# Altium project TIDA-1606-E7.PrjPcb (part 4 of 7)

## Sheet TIDA-1606-Switching-Node-L3-E7.SchDoc
size A2; Date: Not shown in title block; ApprovedBy: Not shown in title block; CheckedBy: Not shown in title block; Author: Not shown in title block; CompanyName: Not shown in title block; Engineer: Not shown in title block; Organization: Not shown in title block; Address1: Not shown in title block; Address2: Not shown in title block; Address3: Not shown in title block; Address4: Not shown in title block; DocumentNumber: 13; Revision: Use project parameter SCH_Rev; SheetNumber: 13; SheetTotal: 16; PageSetup: Record=PageOptions¦CenterHorizontal=True¦CenterVertical=True¦PrintScale=0.69¦XCorrection=1.00¦YCorrection=1.00¦PrintKind=0¦BorderSize=5000000¦LeftOffset=0¦BottomOffset=0¦Orientation=2¦PaperLength=1000¦PaperWidth=1000¦Scale=100¦PaperSource=15¦PrintQuality=600¦MediaType=1¦DitherType=10¦PaperKind=Letter¦PrintScaleMode=1
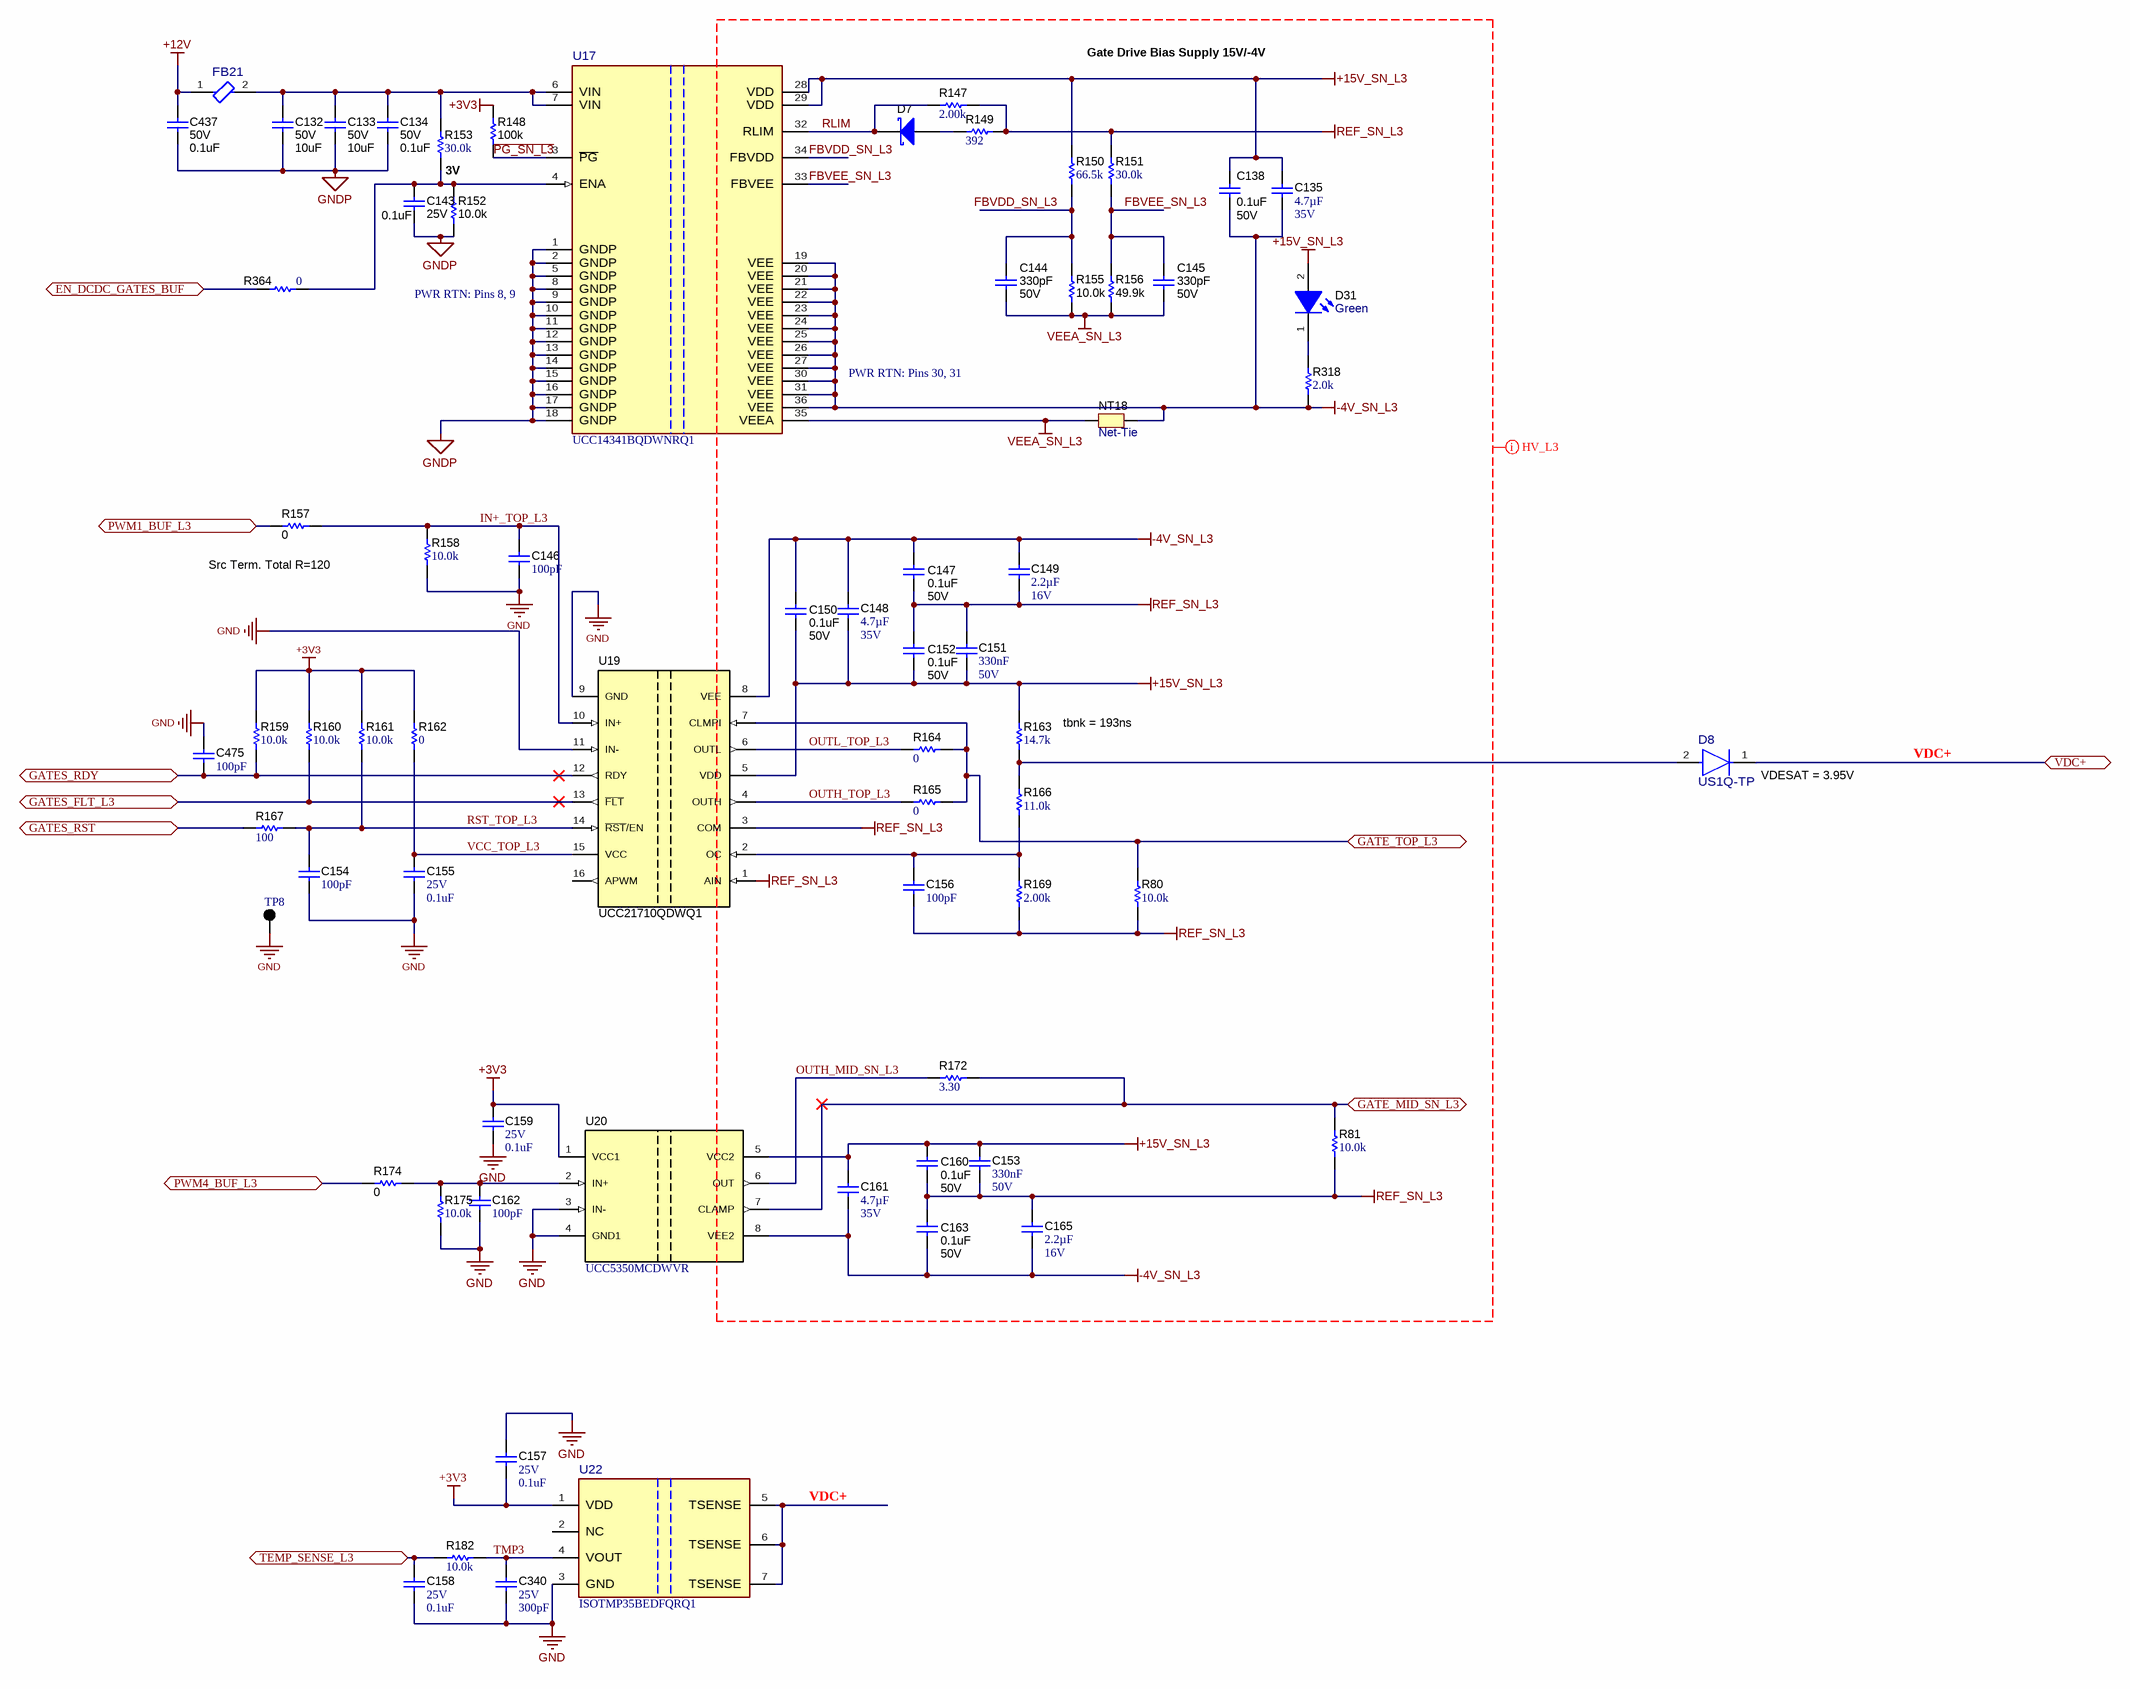
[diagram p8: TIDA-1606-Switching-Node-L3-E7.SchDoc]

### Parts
C132  VDC_V: 50V  ValueDisplayed: 10uF  [1206_180L]  (hidden comment: CL31B106KBHNNNE)
C133  VDC_V: 50V  ValueDisplayed: 10uF  [1206_180L]  (hidden comment: CL31B106KBHNNNE)
C134  VDC_V: 50V  ValueDisplayed: 0.1uF  [0402S]  (hidden comment: GCM155R71H104KE02D)
C135  Cap_F: 4.7µF  VDC_V: 35V  [0805_HV]  (hidden comment: C2012X7R1V475K125AC)
C138  VDC_V: 50V  ValueDisplayed: 0.1uF  [0402L]  (hidden comment: GCM155R71H104KE02D)
C143  VDC_V: 25V  ValueDisplayed: 0.1uF  [0402S]  (hidden comment: GRM155R71E104KE14D)
C144  VDC_V: 50V  ValueDisplayed: 330pF  [0402S]  (hidden comment: CGA2B2X7R1H331K050BA)
C145  VDC_V: 50V  ValueDisplayed: 330pF  [0402S]  (hidden comment: CGA2B2X7R1H331K050BA)
C146  ValueDisplayed: 100pF  [0402L]  (hidden comment: GRM1555C1H101JA01D)
C147  VDC_V: 50V  ValueDisplayed: 0.1uF  [0402L]  (hidden comment: GCM155R71H104KE02D)
C148  Cap_F: 4.7µF  VDC_V: 35V  [0805_HV]  (hidden comment: C2012X7R1V475K125AC)
C149  Cap_F: 2.2µF  VDC_V: 16V  [0603L]  (hidden comment: EMK107BB7225KA-T)
C150  VDC_V: 50V  ValueDisplayed: 0.1uF  [0402L]  (hidden comment: GCM155R71H104KE02D)
C151  Cap_F: 330nF  VDC_V: 50V  [0603L]  (hidden comment: C1608X7R1H334K080AC)
C152  VDC_V: 50V  ValueDisplayed: 0.1uF  [0402L]  (hidden comment: GCM155R71H104KE02D)
C153  Cap_F: 330nF  VDC_V: 50V  [0603L]  (hidden comment: C1608X7R1H334K080AC)
C154  ValueDisplayed: 100pF  [0402L]  (hidden comment: GRM1555C1H101JA01D)
C155  VDC_V: 25V  ValueDisplayed: 0.1uF  [0402L]  (hidden comment: GRM155R71E104KE14D)
C156  ValueDisplayed: 100pF  [0402L]  (hidden comment: GRM1555C1H101JA01D)
C157  VDC_V: 25V  ValueDisplayed: 0.1uF  [0402L]  (hidden comment: GRM155R71E104KE14D)
C158  VDC_V: 25V  ValueDisplayed: 0.1uF  [0402L]  (hidden comment: GRM155R71E104KE14D)
C159  VDC_V: 25V  ValueDisplayed: 0.1uF  [0402L]  (hidden comment: GRM155R71E104KE14D)
C160  VDC_V: 50V  ValueDisplayed: 0.1uF  [0402L]  (hidden comment: GCM155R71H104KE02D)
C161  Cap_F: 4.7µF  VDC_V: 35V  [0805_HV]  (hidden comment: C2012X7R1V475K125AC)
C162  ValueDisplayed: 100pF  [0402L]  (hidden comment: GRM1555C1H101JA01D)
C163  VDC_V: 50V  ValueDisplayed: 0.1uF  [0402L]  (hidden comment: GCM155R71H104KE02D)
C165  Cap_F: 2.2µF  VDC_V: 16V  [0603L]  (hidden comment: EMK107BB7225KA-T)
C340  VDC_V: 25V  ValueDisplayed: 300pF  [0402L]  (hidden comment: GRM1555C1E301JA01D)
C437  VDC_V: 50V  ValueDisplayed: 0.1uF  [0402S]  (hidden comment: GCM155R71H104KE02D)
C475  ValueDisplayed: 100pF  [0402L]  (hidden comment: GRM1555C1H101JA01D)
D7  NSR0130P2T5G  [SOD-923]  (value not drawn)
D8  US1Q-TP  [FP-US1Q-TP_SMA-MFG]
D31  value Green  [WL-SMCW_GREEN]  (hidden comment: 150060VS75000)
FB21  74269244182  [FP-74269244182_0402-MFG]  (value not drawn)
NT18  Net-Tie  [Net-Tie7milsWide_20milsLong]  (net tie, no BOM)
R80  ValueDisplayed: 10.0k  [0402L]  (hidden comment: CRCW040210K0FKED)
R81  ValueDisplayed: 10.0k  [0402L]  (hidden comment: CRCW040210K0FKED)
R147  ValueDisplayed: 2.00k  [0402L]  (hidden comment: CRCW04022K00FKED)
R148  ValueDisplayed: 100k  [0402S]  (hidden comment: ERJ-2GEJ104X)
R149  ValueDisplayed: 392  [0402L]  (hidden comment: CRCW0402392RFKED)
R150  ValueDisplayed: 66.5k  [0402L]  (hidden comment: CRCW040266K5FKED)
R151  ValueDisplayed: 30.0k  [0402L]  (hidden comment: CRCW040230K0FKED)
R152  ValueDisplayed: 10.0k  [0402S]  (hidden comment: MCS0402MD1002BE100)
R153  ValueDisplayed: 30.0k  [0402L]  (hidden comment: CRCW040230K0FKED)
R155  ValueDisplayed: 10.0k  [0402S]  (hidden comment: MCS0402MD1002BE100)
R156  ValueDisplayed: 49.9k  [0402S]  (hidden comment: PCF0402-03-49K9BT1)
R157  ValueDisplayed: 0  [0603L]  (hidden comment: RCS06030000Z0EA)
R158  ValueDisplayed: 10.0k  [0402L]  (hidden comment: CRCW040210K0FKED)
R159  ValueDisplayed: 10.0k  [0402L]  (hidden comment: CRCW040210K0FKED)
R160  ValueDisplayed: 10.0k  [0402L]  (hidden comment: CRCW040210K0FKED)
R161  ValueDisplayed: 10.0k  [0402L]  (hidden comment: CRCW040210K0FKED)
R162  ValueDisplayed: 0  [0603L]  (hidden comment: RC0603JR-070RL)
R163  ValueDisplayed: 14.7k  [0603L]  (hidden comment: ERJ-3EKF1472V)
R164  ValueDisplayed: 0  [1206]  (hidden comment: CRCW12060000Z0EA)
R165  ValueDisplayed: 0  [1206]  (hidden comment: CRCW12060000Z0EA)
R166  ValueDisplayed: 11.0k  [0603L]  (hidden comment: RC0603FR-0711KL)
R167  ValueDisplayed: 100  [0402L]  (hidden comment: ERJ-2RKF1000X)
R169  ValueDisplayed: 2.00k  [0402L]  (hidden comment: CRCW04022K00FKED)
R172  ValueDisplayed: 3.30  [1206]  (hidden comment: ERJ-8RQF3R3V)
R174  ValueDisplayed: 0  [0603L]  (hidden comment: RCS06030000Z0EA)
R175  ValueDisplayed: 10.0k  [0402L]  (hidden comment: CRCW040210K0FKED)
R182  ValueDisplayed: 10.0k  [0402L]  (hidden comment: CRCW040210K0FKED)
R318  ValueDisplayed: 2.0k  [1206]  (hidden comment: CRCW12062K00JNEA)
R364  ValueDisplayed: 0  [0402L]  (hidden comment: RC0402JR-070RL)
TP8  5001  [Keystone5001]  (value not drawn)
U17  UCC14341BQDWNRQ1  [DWN0036A-MFG]
U19  UCC21710QDWQ1  [DW0016B_HV]
U20  UCC5350MCDWVR  [DWV0008A]
U22  ISOTMP35BEDFQRQ1  [DFQ0007A-MFG]

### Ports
EN_DCDC_GATES_BUF (bidir), GATE_MID_SN_L3 (bidir), GATE_TOP_L3 (bidir), GATES_FLT_L3 (bidir), GATES_RDY (bidir), GATES_RST (bidir), PWM1_BUF_L3 (bidir), PWM4_BUF_L3 (bidir), TEMP_SENSE_L3 (bidir), VDC+ (bidir)

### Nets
+3V3: C157.2 C159.1 R148.2 R159.2 R160.2 R161.2 R162.2 U20.1(VCC1) U22.1(VDD)
+12V: C437.1 FB21.1
+15V_SN_L3: C135.1 C138.2 C148.2 C150.1 C151.2 C152.1 C153.1 C160.2 C161.1 D31.2(A) R150.2 R163.2 U17.28(VDD) U17.29(VDD) U19.5(VDD) U20.5(VCC2)
-4V_SN_L3: C135.2 C138.1 C147.2 C148.1 C149.1 C150.2 C161.2 C163.1 C165.2 NT18.1 R318.1 U17.19(VEE) U17.20(VEE) U17.21(VEE) U17.22(VEE) U17.23(VEE) U17.24(VEE) U17.25(VEE) U17.26(VEE) U17.27(VEE) U17.30(VEE) U17.31(VEE) U17.36(VEE) U19.8(VEE) U20.8(VEE2)
GND: C132.2 C133.2 C134.2 C143.2 C146.2 C154.2 C155.2 C157.1 C158.2 C159.2 C162.2 C340.1 C437.2 C475.1 R152.1 R158.1 R175.2 TP8.1 U17.1(GNDP) U17.2(GNDP) U17.5(GNDP) U17.8(GNDP) U17.9(GNDP) U17.10(GNDP) U17.11(GNDP) U17.12(GNDP) U17.13(GNDP) U17.14(GNDP) U17.15(GNDP) U17.16(GNDP) U17.17(GNDP) U17.18(GNDP) U19.9(GND) U19.11(IN-) U20.3(IN-) U20.4(GND1) U22.3(GND)  [also labelled GNDP]
REF_SN_L3: C147.1 C149.2 C151.1 C152.2 C153.2 C156.2 C160.1 C163.2 C165.1 R80.1 R81.1 R147.1 R149.2 R151.2 R169.1 U19.1(AIN) U19.3(COM)
VDC+: D8.1(CATHODE) U22.5(TSENSE) U22.6(TSENSE) U22.7(TSENSE) ; port VDC+
VEEA_SN_L3: C144.2 C145.2 NT18.2 R155.1 R156.1 U17.35(VEEA)
~{PG_SN_L3}: R148.1 U17.3(~{PG})
EN_DCDC_GATES_BUF: R364.1 ; port EN_DCDC_GATES_BUF
FBVDD_SN_L3: C144.1 R150.1 R155.2 U17.34(FBVDD)
FBVEE_SN_L3: C145.1 R151.1 R156.2 U17.33(FBVEE)
GATE_MID_SN_L3: R81.2 R172.2 U20.7(CLAMP) ; port GATE_MID_SN_L3
GATE_TOP_L3: R80.2 R164.2 R165.2 U19.7(CLMPI) ; port GATE_TOP_L3
GATES_FLT_L3: R160.1 U19.13(~{FLT}) ; port GATES_FLT_L3
GATES_RDY: C475.2 R159.1 U19.12(RDY) ; port GATES_RDY
GATES_RST: R167.1 ; port GATES_RST
IN+_TOP_L3: C146.1 R157.1 R158.2 U19.10(IN+)
OUTH_MID_SN_L3: R172.1 U20.6(OUT)
OUTH_TOP_L3: R165.1 U19.4(OUTH)
OUTL_TOP_L3: R164.1 U19.6(OUTL)
PWM1_BUF_L3: R157.2 ; port PWM1_BUF_L3
PWM4_BUF_L3: R174.2 ; port PWM4_BUF_L3
RLIM: D7.1(K) R147.2 U17.32(RLIM)
RST_TOP_L3: C154.1 R161.1 R167.2 U19.14(~{RST}/EN)
TEMP_SENSE_L3: C158.1 R182.2 ; port TEMP_SENSE_L3
TMP3: C340.2 R182.1 U22.4(VOUT)
VCC_TOP_L3: C155.1 R162.1 U19.15(VCC)
NetC132_1: C132.1 C133.1 C134.1 FB21.2 R153.2 U17.6(VIN) U17.7(VIN)
NetC143_1: C143.1 R152.2 R153.1 R364.2 U17.4(ENA)
NetC156_1: C156.1 R166.1 R169.2 U19.2(OC)
NetC162_1: C162.1 R174.1 R175.1 U20.2(IN+)
NetD7_2: D7.2(A) R149.1
NetD8_2: D8.2(ANODE) R163.1 R166.2
NetD31_1: D31.1(K) R318.2

Not connected (* = marked no-connect by the designer): U19 16(APWM); U22 2(NC)

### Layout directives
net class HV_L3; net class HV_Nets: +15V_SN_L3, -4V_SN_L3, FBVDD_SN_L3, FBVEE_SN_L3, OUTH_MID_SN_L3, OUTH_TOP_L3, OUTL_TOP_L3, REF_SN_L3, RLIM, VEEA_SN_L3

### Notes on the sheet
- Gate Drive Bias Supply 15V/-4V
- (near R153) 3V
- PWR RTN: Pins 8, 9
- PWR RTN: Pins 30, 31
- (near R157) Src Term. Total R=120
- (near R163) tbnk = 193ns
- (near D8) VDESAT = 3.95V

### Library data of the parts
C132 C133 = CMP-0008802-2: CAP, CERM, 10 uF, 50 V, +/- 10%, X7R, 1206; Manufacturer: Samsung; TaMin_C: -55°C; Polarized: N; SizeAreaWB_mm2: 10.92; Value1: Unknown; U/M: EA; Value: 10uF; TaMax_C: 125°C; SizeZ_mm: 1.8; SizeX_mm: 3.2; SizeY_mm: 1.6; Cap_Case: 1206; SizeArea_mm2: 5.12; Cap_F: 10µF; AEC Category: Q200
C134 C138 C147 C150 C152 C160 C163 C437 = CMP-0006356-2: CAP, CERM, 0.1 uF, 50 V, +/- 10%, X7R, AEC-Q200 Grade 1, 0402; Manufacturer: MuRata; TaMin_C: -55°C; Polarized: N; SizeAreaWB_mm2: 3; Value1: Unknown; U/M: EA; Value: 0.1uF; TaMax_C: 125°C; SizeZ_mm: 0.6; SizeX_mm: 1; SizeY_mm: 0.5; Cap_Case: 0402; AEC Qualified: Y; Cap_F: 100nF; AEC Category: Q200
C135 C148 C161 = CMP-0007885-2: CAP, CERM, 4.7 uF, 35 V, +/- 10%, X7R, 0805; Manufacturer: TDK; TaMin_C: -55°C; ESR_ohm: 2.346m; Polarized: N; SizeAreaWB_mm2: 6.75; Value1: 0.002346 ohm; U/M: EA; Value: 4.7uF; TaMax_C: 125°C; SizeZ_mm: 1.45; SizeX_mm: 2; SizeY_mm: 1.25; Cap_Case: 0805; SizeArea_mm2: 2.5; IRMS_A: 4.26021A; AEC Category: Q200
C143 C155 C157-C159 = CMP-0006659-2: CAP, CERM, 0.1 uF, 25 V, +/- 10%, X7R, 0402; Manufacturer: MuRata; TaMin_C: -55°C; Polarized: N; SizeAreaWB_mm2: 3; Value1: Unknown; U/M: EA; Value: 0.1uF; TaMax_C: 125°C; SizeZ_mm: 0.6; SizeX_mm: 1; SizeY_mm: 0.5; Cap_Case: 0402; Cap_F: 100nF; AEC Category: Q200
C144 C145 = CMP-0006318-2: CAP, CERM, 330 pF, 50 V, +/- 10%, X7R, AEC-Q200 Grade 1, 0402; Manufacturer: TDK; TaMin_C: -55°C; ESR_ohm: 6.53276; Polarized: N; SizeAreaWB_mm2: 3; Value1: 6.53276 ohm; U/M: EA; Value: 330pF; TaMax_C: 125°C; SizeZ_mm: 0.6; SizeX_mm: 1; SizeY_mm: 0.5; Cap_Case: 0402; AEC Qualified: Y; IRMS_A: 2.12649dA; AEC Category: Q200
C146 C154 C156 C162 C475 = CMP-0006410-2: CAP, CERM, 100 pF, 50 V, +/- 5%, C0G/NP0, 0402; Manufacturer: MuRata; TaMin_C: -55°C; Polarized: N; SizeAreaWB_mm2: 3; Value1: Unknown; U/M: EA; Value: 100pF; TaMax_C: 125°C; SizeZ_mm: 0.6; SizeX_mm: 1; SizeY_mm: 0.5; Cap_Case: 0402; Value2: 50V; AEC Category: Q200
C149 C165 = CMP-0007121-4: CAP, CERM, 2.2 uF, 16 V, +/- 10%, X7R, 0603; Manufacturer: Taiyo Yuden; TaMin_C: -55°C; Polarized: N; SizeAreaWB_mm2: 4.68; Value1: Unknown; U/M: EA; Value: 2.2uF; TaMax_C: 125°C; SizeZ_mm: 1; SizeX_mm: 1.6; SizeY_mm: 0.8; Cap_Case: 0603; SizeArea_mm2: 1.28; AEC Category: Q200
C151 C153 = CMP-0007048-4: CAP, CERM, 0.33 uF, 50 V, +/- 10%, X7R, 0603; Manufacturer: TDK; TaMin_C: -55°C; ESR_ohm: 0.016574; Polarized: N; SizeAreaWB_mm2: 4.68; Value1: 0.016574 ohm; U/M: EA; Value: 0.33uF; TaMax_C: 125°C; SizeZ_mm: 1; SizeX_mm: 1.6; SizeY_mm: 0.8; Cap_Case: 0603; SizeArea_mm2: 1.28; IRMS_A: 1.28367A; AEC Category: Q200
C340 = CMP-0006376-2: CAP, CERM, 300 pF, 25 V, +/- 5%, C0G/NP0, 0402; Manufacturer: MuRata; TaMin_C: -55°C; Polarized: N; SizeAreaWB_mm2: 3; Value1: Unknown; U/M: EA; Value: 300pF; TaMax_C: 125°C; SizeZ_mm: 0.6; SizeX_mm: 1; SizeY_mm: 0.5; Cap_Case: 0402; AEC Category: Q200
D7 = CMP-0077005-2: Diode, Schottky, 30 V, 0.1 A, SOD-923; Manufacturer: ON Semiconductor; AEC Category: Q101; Value1: 0.1A; SizeZ_mm: 0.4; Vr_V: 30V; Vf_V: 525mV; SizeX_mm: 1.0; Value2: 0.525V; SizeY_mm: 0.6; Green_Lifecycle: Not Set; TJmax_C: 125°C; Value: 30V; Io_A: 100mA; SizeAreaWB_mm2: 3.2; Green_REACh: Incomplete
D8 = CMP-0095286-1: Diode Standard 1200 V 1A Surface Mount DO-214AC (SMA); Manufacturer: MCC; Cap_F: 45pF; Max Surge Forward Current: 30A; SizeZ_mm: 2.44mm; TJmax_C: 150°C; Vr_V: 1.2kV; Peak Reverse Current: 5uA; AEC Qualified: No
D31 = CMP-0002894-2: LED, Green, SMD; Manufacturer: Wurth Elektronik; Type: AlInGaP; Value2: 2V; Io_A: 20mA; Value1: W
FB21 = CMP-0091663-1: 1.8 kOhms @ 100MHz 1 Power, Signal Line Ferrite Bead 0402 (1005 Metric) 210mA 2.1Ohm; Manufacturer: Wurth Electronics; SizeZ_mm: 0.55mm; AEC Qualified: No; DCR_ohm: 2.1; Tolerance_%: 25%; Test Frequency: 1GHz; Impedance At Frequency: 1800Ω @ 100MHz
NT18 = CMP-0078142-6: Single point connection between nets.
R80 R81 R158-R161 R175 R182 = CMP-0025958-3: RES, 10.0 k, 1%, 0.063 W, AEC-Q200 Grade 0, 0402; Manufacturer: Vishay-Dale; Power_W: 63mW; TempCo: 100 ppm/C; Value_Code: 10k0; Value: 10.0k; EIA_Code: E96; Res_ohm: 10k; SizeX_mm: 1; SizeY_mm: 0.5; SizeZ_mm: 0.6; Value2: 0.063W; AEC Qualified: Y; VDC_V: 50V; AEC Category: Q200; AEC Grade: 0
R147 R169 = CMP-0026227-2: RES, 2.00 k, 1%, 0.063 W, AEC-Q200 Grade 0, 0402; Manufacturer: Vishay-Dale; Power_W: 63mW; TempCo: 100 ppm/C; Value_Code: 2k00; Value: 2.00k; EIA_Code: E96; Res_ohm: 2k; SizeX_mm: 1; SizeY_mm: 0.5; SizeZ_mm: 0.6; Value2: 0.063W; AEC Qualified: Y; VDC_V: 50V; AEC Category: Q200; AEC Grade: 0
R148 = CMP-0026995-2: RES, 100 k, 5%, 0.1 W, AEC-Q200 Grade 0, 0402; Manufacturer: Panasonic; Power_W: 100mW; TempCo: 200 ppm/C; U/M: EA; Value: 100k; EIA_Code: E24; SizeX_mm: 1; SizeY_mm: 0.5; SizeZ_mm: 0.6; Value2: 0.1W; AEC Qualified: Y; VDC_V: 50V; AEC Grade: 0; AEC Category: Q200
R149 = CMP-0026326-2: RES, 392, 1%, 0.063 W, AEC-Q200 Grade 0, 0402; Manufacturer: Vishay-Dale; Power_W: 63mW; TempCo: 100 ppm/C; Value_Code: 392R; Value: 392; EIA_Code: E96; SizeX_mm: 1; SizeY_mm: 0.5; SizeZ_mm: 0.6; Value2: 0.063W; AEC Qualified: Y; VDC_V: 50V; AEC Category: Q200; AEC Grade: 0
R150 = CMP-0026502-2: RES, 66.5 k, 1%, 0.063 W, AEC-Q200 Grade 0, 0402; Manufacturer: Vishay-Dale; Power_W: 63mW; TempCo: 100 ppm/C; Value_Code: 66k5; Value: 66.5k; EIA_Code: E96; SizeX_mm: 1; SizeY_mm: 0.5; SizeZ_mm: 0.6; Value2: 0.063W; AEC Qualified: Y; VDC_V: 50V; AEC Category: Q200; AEC Grade: 0
R151 R153 = CMP-0078244-2: RES, 30.0 k, 1%, 0.063 W, AEC-Q200 Grade 0, 0402; Manufacturer: Vishay-Dale; Power_W: 63mW; Green_Lifecycle: Active; TempCo: 100 ppm/C; Value_Code: 30k0; Green_REACh: Passed; Value: 30.0k; Res_ohm: 30k; SizeX_mm: 1; SizeY_mm: 0.5; SizeZ_mm: 0.6; Value2: 0.063W; AEC Qualified: Y; VDC_V: 50V; AEC Grade: 0; AEC Category: Q200
R152 R155 = CMP-0077124-1: RES, 10.0 k, 0.1%, 0.1 W, AEC-Q200 Grade 0, 0402; Manufacturer: Vishay/Beyschlag; Value_Code: 10k0; SizeArea_mm2: 0.5; AEC Qualified: Y; AEC Category: Q200; Res_ohm: 10k; Value: 10.0k; SizeZ_mm: 0.6; EIA_Code: E192; TempCo: 25 ppm/C; AEC Grade: 0; Power_W: 100mW; VDC_V: 50V; Value2: 0.1W; U/M: EA; SizeX_mm: 1.0
R156 = CMP-0026795-1: RES, 49.9 k, 0.1%, 0.063 W, 0402; Manufacturer: TT Electronics/IRC; Power_W: 63mW; TempCo: 25 ppm/C; Value_Code: 49k9; U/M: EA; Value: 49.9k; EIA_Code: E192; SizeX_mm: 1; SizeY_mm: 0.5; SizeZ_mm: 0.6; Value2: 0.063W; AEC Qualified: N; VDC_V: 25V; AEC Category: Q200
R157 R174 = CMP-0081973-1: RES, 0, 0%, 0.25 W, AEC-Q200 Grade 0, 0603; Manufacturer: Vishay-Dale; SizeAreaWB_mm2: 4.68; SizeArea_mm2: 1.28; AEC Qualified: Y; AEC Category: Q200; Value: 0; SizeZ_mm: 1; SizeY_mm: 0.8; Power_W: 250mW; Value2: 0.25W; SizeX_mm: 1.6
R162 = CMP-0025885-5: RES, 0, 5%, 0.1 W, 0603; Manufacturer: Yageo; Power_W: 100mW; TempCo: 200 ppm/C; Value_Code: 0000; Value: 0; EIA_Code: E24; SizeX_mm: 1.6; SizeZ_mm: 1; Value2: 0.1W; SizeArea_mm2: 1.28; AEC Qualified: N; VDC_V: 75V; AEC Category: Q200; SizeY_mm: 0.8; SizeAreaWB_mm2: 4.68
R163 = CMP-0022687-3: RES, 14.7 k, 1%, 0.1 W, AEC-Q200 Grade 0, 0603; Manufacturer: Panasonic; Power_W: 100mW; TempCo: 100 ppm/C; Value_Code: 14k7; U/M: EA; Value: 14.7k; EIA_Code: E96; SizeX_mm: 1.6; SizeY_mm: 0.8; SizeZ_mm: 1; Value2: 0.1W; SizeArea_mm2: 1.28; AEC Qualified: Y; VDC_V: 50V; AEC Grade: 0; AEC Category: Q200
R164 R165 = CMP-0018573-3: RES, 0, 5%, 0.25 W, AEC-Q200 Grade 0, 1206; Manufacturer: Vishay-Dale; Power_W: 250mW; TempCo: 200 ppm/C; Value_Code: 0000; Value: 0; EIA_Code: E24; SizeX_mm: 3.2; SizeY_mm: 1.6; SizeZ_mm: 1.35; Value2: 0.25W; SizeArea_mm2: 5.12; AEC Qualified: Y; VDC_V: 200V; AEC Category: Q200
R166 = CMP-0022763-5: RES, 11.0 k, 1%, 0.1 W, 0603; Manufacturer: Yageo; Power_W: 100mW; TempCo: 100 ppm/C; Value_Code: 11k0; Value: 11.0k; EIA_Code: E96; Res_ohm: 11k; SizeX_mm: 1.6; SizeY_mm: 0.8; SizeZ_mm: 1; Value2: 0.1W; SizeArea_mm2: 1.28; AEC Qualified: N; VDC_V: 75V; AEC Category: Q200; SizeAreaWB_mm2: 4.68
R167 = CMP-0026656-1: RES, 100, 1%, 0.1 W, 0402; Manufacturer: Panasonic; Power_W: 100mW; TempCo: 100 ppm/C; Value_Code: 100R; U/M: EA; Value: 100; EIA_Code: E96; SizeX_mm: 1; SizeY_mm: 0.5; SizeZ_mm: 0.6; Value2: 0.1W; VDC_V: 50V; AEC Category: Q200
R172 = CMP-0017779-3: RES, 3.30, 1%, 0.25 W, AEC-Q200 Grade 0, 1206; Manufacturer: Panasonic; Power_W: 250mW; TempCo: 200 ppm/C; Value_Code: 3R30; Value: 3.30; Res_ohm: 3.3; SizeX_mm: 3.2; SizeY_mm: 1.6; SizeZ_mm: 1.35; Value2: 0.25W; SizeArea_mm2: 5.12; AEC Qualified: Y; AEC Category: Q200; AEC Grade: 0; SizeAreaWB_mm2: 10.92
R318 = CMP-0018640-3: RES, 2.0 k, 5%, 0.25 W, AEC-Q200 Grade 0, 1206; Manufacturer: Vishay-Dale; Power_W: 250mW; TempCo: 200 ppm/C; Value_Code: 2k00; Value: 2.0k; EIA_Code: E24; Res_ohm: 2k; SizeX_mm: 3.2; SizeY_mm: 1.6; SizeZ_mm: 1.35; Value2: 0.25W; SizeArea_mm2: 5.12; AEC Qualified: Y; VDC_V: 200V; AEC Category: Q200; AEC Grade: 0
R364 = CMP-0027004-2: RES, 0, 5%, 0.063 W, 0402; Manufacturer: Yageo America; Power_W: 63mW; TempCo: 200 ppm/C; Value_Code: 0000; U/M: EA; Value: 0; EIA_Code: E24; SizeX_mm: 1; SizeY_mm: 0.5; SizeZ_mm: 0.6; Value2: 0.063W; VDC_V: 50V; AEC Category: Q200
TP8 = CMP-0055138-2: Test Point, Miniature, Black, TH; Manufacturer: Keystone Electronics; ContactFinish: Silver; CNHeader: FALSE; Green_Lifecycle: Active; Green_REACh: Passed; CT: TRUE
U17 = CMP-0121477-1: Automotive 1.5-W, 15-V VIN, 25-V VOUT, High-Density, > 5 kVRMS, Isolated DC/DC Module; Manufacturer: Texas Instruments; SizeZ_mm: 3.55mm; AEC Qualified: Yes; AEC Grade: Grade 1; Max Supply Voltage: 16.5V; Min Supply Voltage: 13.5V; Nominal Supply Current: 190mA; Number Of Outputs: 1; Output Type: AdjustableProgrammable; Output Voltage: 15-25V; Standoff Height: 0.1mm; Switching Frequency: 15MHz; TaMax_C: +125°C; TaMin_C: -40°C; TJmax_C: +150°C
U19 = CMP-0080534-2: Single Channel Isolated Gate Driver for SiC/IGBT with Advanced Protection and High-CMTI, DW0016B (SOIC-16); Manufacturer: Texas Instruments; Alternate PartNumber: UCC21710QDWRQ1; SizeY_mm: 10.3; CompType: IC; AEC Qualified: Y; SizeArea_mm2: 107.12; SizeAreaWB_mm2: 152.52; SizeZ_mm: 2.65; SizeX_mm: 10.4; AEC Category: Q200
U20 = CMP-0078841-1: 5-kVRMS Single-Channel Isolated Gate Drivers, DWV0008A (SOIC-8); Alternate Manufacturer: Texas Instruments; SizeAreaWB_mm2: 105.975; SizeZ_mm: 2.8; SizeX_mm: 11.5; SizeY_mm: 5.85; SizeArea_mm2: 67.275; CompType: IC; AEC Qualified: N; AEC Category: Q200
U22 = CMP-0122473-1: Automotive ±1.5°C, 3-kVRMS Isolated Temperature Sensor With Analog Output With < 2 Seconds Response Time and 500VRMS Working Voltage; Manufacturer: Texas Instruments; SizeZ_mm: 1.75mm; AEC Qualified: Yes; AEC Grade: Grade 0; Max Supply Voltage: 5.5V; Min Supply Voltage: 2.3V; Operating Supply Current: 10uA; Sensor Output: Analog Voltage; Standoff Height: 0.11mm; TaMax_C: +150°C; TaMin_C: -40°C; TJmax_C: +155°C

## Sheet TIDA-1606-Low-Side-E7.SchDoc
size A2; Date: Not shown in title block; ApprovedBy: Not shown in title block; CheckedBy: Not shown in title block; Author: Not shown in title block; CompanyName: Not shown in title block; Engineer: Not shown in title block; Organization: Not shown in title block; Address1: Not shown in title block; Address2: Not shown in title block; Address3: Not shown in title block; Address4: Not shown in title block; DocumentNumber: 9; Revision: Use project parameter SCH_Rev; SheetNumber: 9; SheetTotal: 16; PageSetup: Record=PageOptions¦CenterHorizontal=True¦CenterVertical=True¦PrintScale=0.69¦XCorrection=1.00¦YCorrection=1.00¦PrintKind=0¦BorderSize=5000000¦LeftOffset=0¦BottomOffset=0¦Orientation=2¦PaperLength=1000¦PaperWidth=1000¦Scale=100¦PaperSource=15¦PrintQuality=600¦MediaType=1¦DitherType=10¦PaperKind=Letter¦PrintScaleMode=1
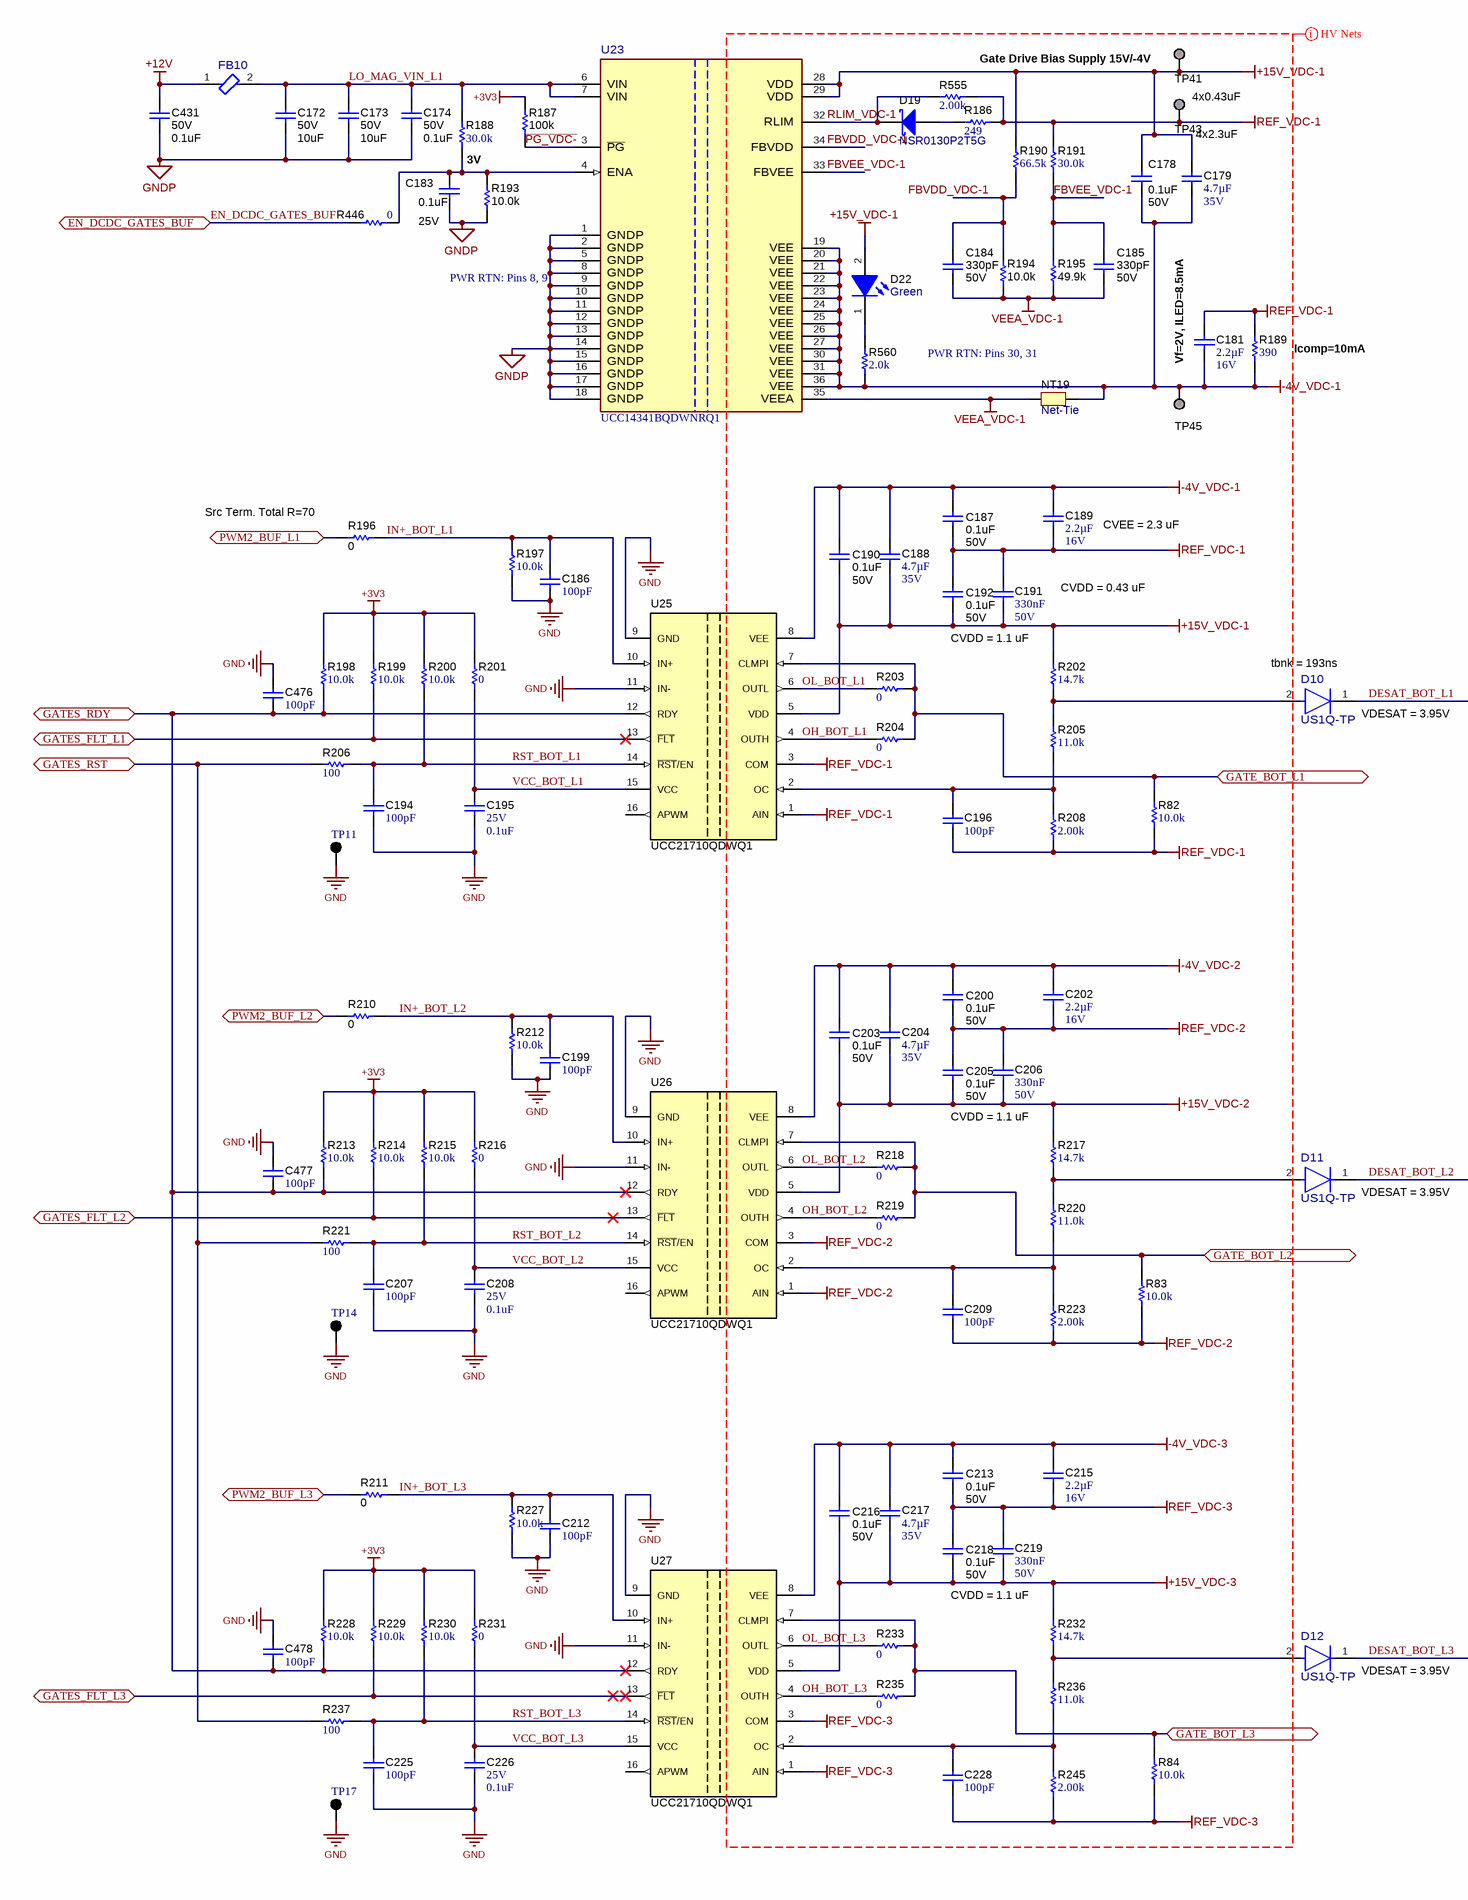
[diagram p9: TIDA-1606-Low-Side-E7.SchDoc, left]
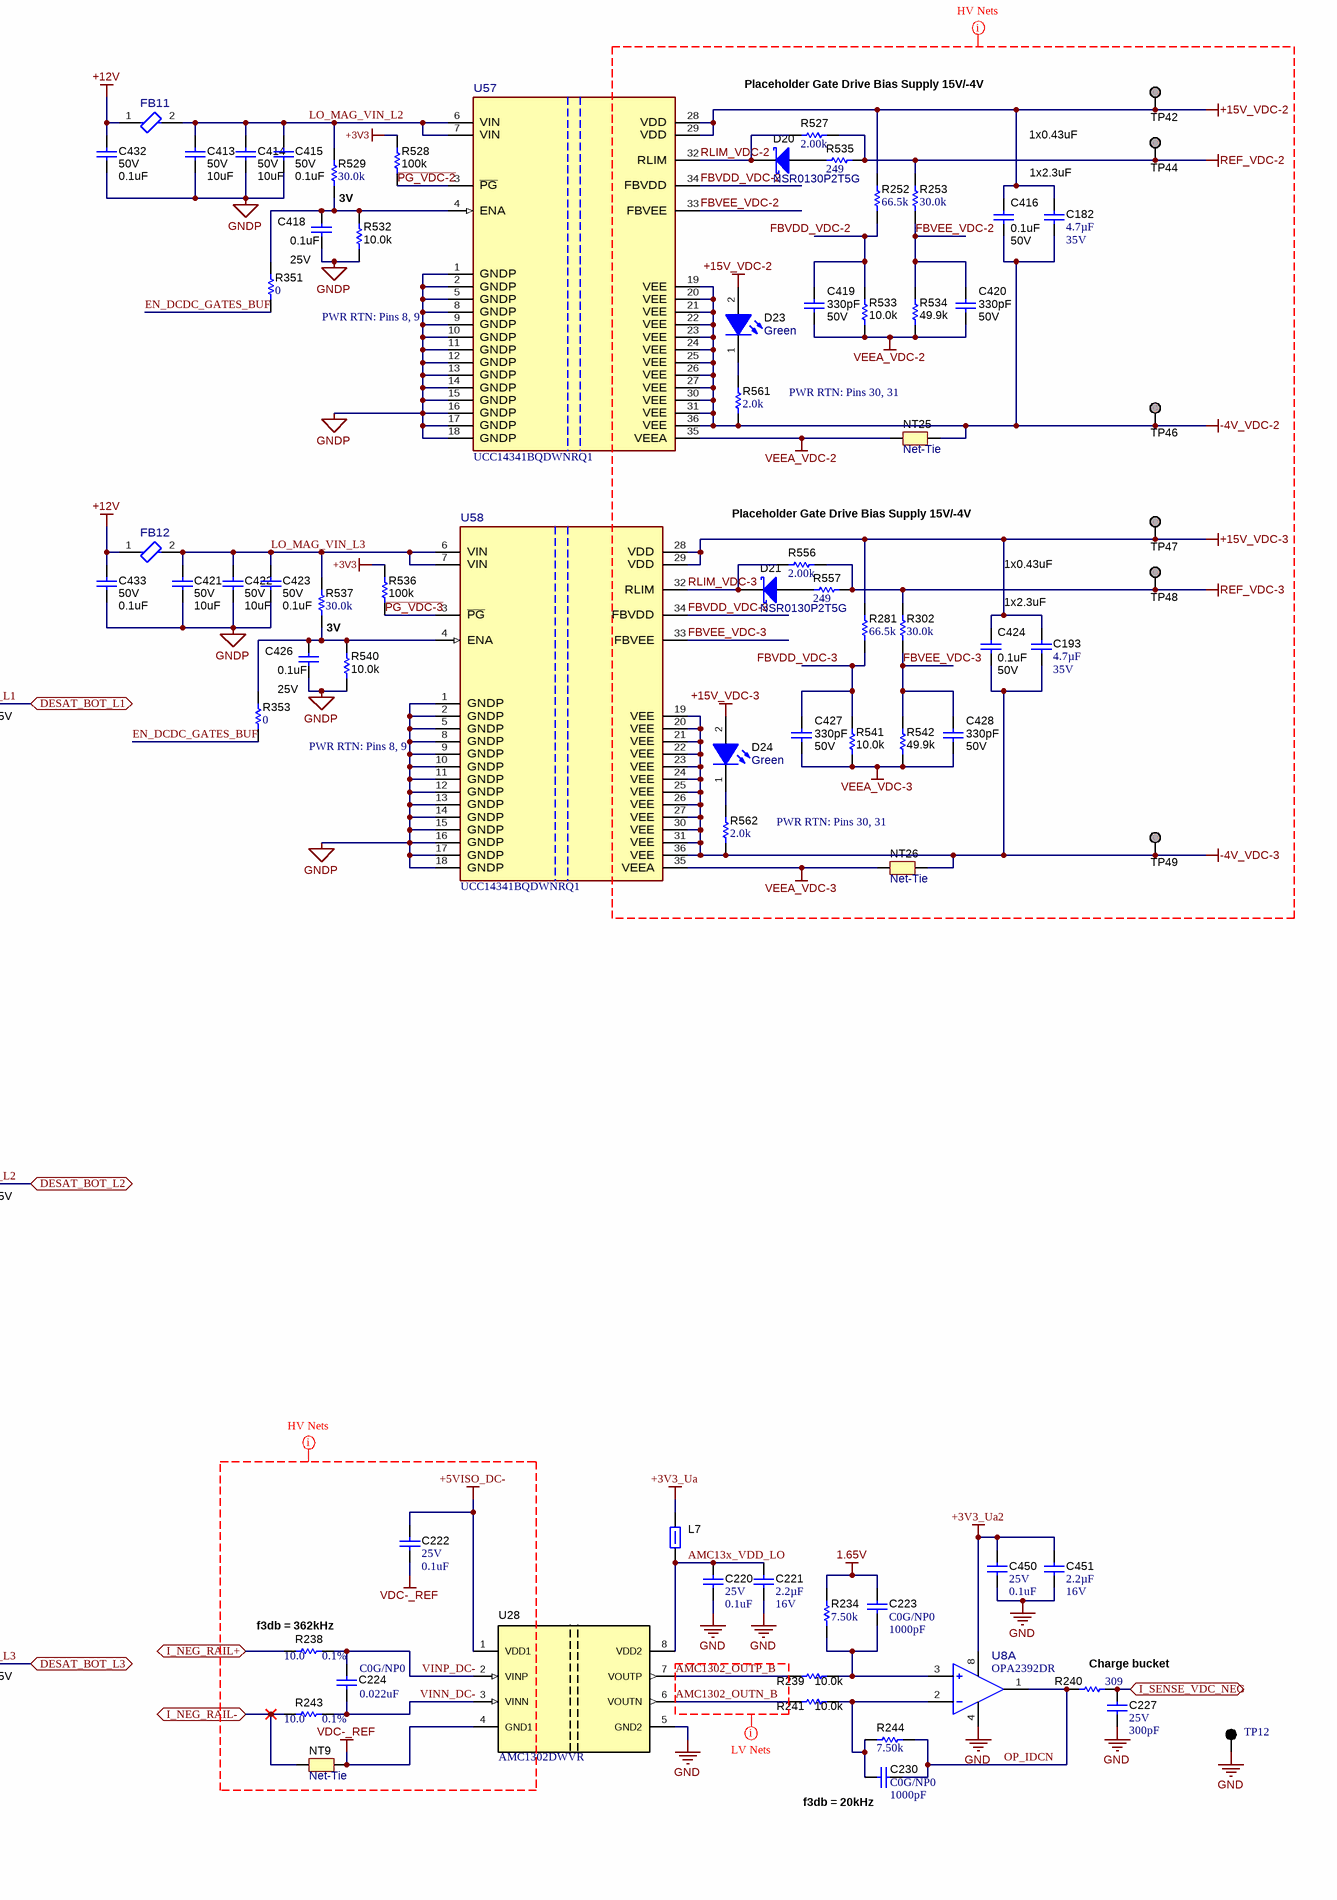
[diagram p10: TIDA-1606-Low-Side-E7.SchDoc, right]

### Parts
C172  VDC_V: 50V  ValueDisplayed: 10uF  [1206_180L]  (hidden comment: CL31B106KBHNNNE)
C173  VDC_V: 50V  ValueDisplayed: 10uF  [1206_180L]  (hidden comment: CL31B106KBHNNNE)
C174  VDC_V: 50V  ValueDisplayed: 0.1uF  [0402S]  (hidden comment: GCM155R71H104KE02D)
C178  VDC_V: 50V  ValueDisplayed: 0.1uF  [0402L]  (hidden comment: GCM155R71H104KE02D)
C179  Cap_F: 4.7µF  VDC_V: 35V  [0805_HV]  (hidden comment: C2012X7R1V475K125AC)
C181  Cap_F: 2.2µF  VDC_V: 16V  [0603L]  (hidden comment: EMK107BB7225KA-T)
C182  Cap_F: 4.7µF  VDC_V: 35V  [0805_HV]  (hidden comment: C2012X7R1V475K125AC)
C183  VDC_V: 25V  ValueDisplayed: 0.1uF  [0402S]  (hidden comment: GRM155R71E104KE14D)
C184  VDC_V: 50V  ValueDisplayed: 330pF  [0402S]  (hidden comment: CGA2B2X7R1H331K050BA)
C185  VDC_V: 50V  ValueDisplayed: 330pF  [0402S]  (hidden comment: CGA2B2X7R1H331K050BA)
C186  ValueDisplayed: 100pF  [0402L]  (hidden comment: GRM1555C1H101JA01D)
C187  VDC_V: 50V  ValueDisplayed: 0.1uF  [0402L]  (hidden comment: GCM155R71H104KE02D)
C188  Cap_F: 4.7µF  VDC_V: 35V  [0805_HV]  (hidden comment: C2012X7R1V475K125AC)
C189  Cap_F: 2.2µF  VDC_V: 16V  [0603L]  (hidden comment: EMK107BB7225KA-T)
C190  VDC_V: 50V  ValueDisplayed: 0.1uF  [0402L]  (hidden comment: GCM155R71H104KE02D)
C191  Cap_F: 330nF  VDC_V: 50V  [0603L]  (hidden comment: C1608X7R1H334K080AC)
C192  VDC_V: 50V  ValueDisplayed: 0.1uF  [0402L]  (hidden comment: GCM155R71H104KE02D)
C193  Cap_F: 4.7µF  VDC_V: 35V  [0805_HV]  (hidden comment: C2012X7R1V475K125AC)
C194  ValueDisplayed: 100pF  [0402L]  (hidden comment: GRM1555C1H101JA01D)
C195  VDC_V: 25V  ValueDisplayed: 0.1uF  [0402L]  (hidden comment: GRM155R71E104KE14D)
C196  ValueDisplayed: 100pF  [0402L]  (hidden comment: GRM1555C1H101JA01D)
C199  ValueDisplayed: 100pF  [0402L]  (hidden comment: GRM1555C1H101JA01D)
C200  VDC_V: 50V  ValueDisplayed: 0.1uF  [0402L]  (hidden comment: GCM155R71H104KE02D)
C202  Cap_F: 2.2µF  VDC_V: 16V  [0603L]  (hidden comment: EMK107BB7225KA-T)
C203  VDC_V: 50V  ValueDisplayed: 0.1uF  [0402L]  (hidden comment: GCM155R71H104KE02D)
C204  Cap_F: 4.7µF  VDC_V: 35V  [0805_HV]  (hidden comment: C2012X7R1V475K125AC)
C205  VDC_V: 50V  ValueDisplayed: 0.1uF  [0402L]  (hidden comment: GCM155R71H104KE02D)
C206  Cap_F: 330nF  VDC_V: 50V  [0603L]  (hidden comment: C1608X7R1H334K080AC)
C207  ValueDisplayed: 100pF  [0402L]  (hidden comment: GRM1555C1H101JA01D)
C208  VDC_V: 25V  ValueDisplayed: 0.1uF  [0402L]  (hidden comment: GRM155R71E104KE14D)
C209  ValueDisplayed: 100pF  [0402L]  (hidden comment: GRM1555C1H101JA01D)
C212  ValueDisplayed: 100pF  [0402L]  (hidden comment: GRM1555C1H101JA01D)
C213  VDC_V: 50V  ValueDisplayed: 0.1uF  [0402L]  (hidden comment: GCM155R71H104KE02D)
C215  Cap_F: 2.2µF  VDC_V: 16V  [0603L]  (hidden comment: EMK107BB7225KA-T)
C216  VDC_V: 50V  ValueDisplayed: 0.1uF  [0402L]  (hidden comment: GCM155R71H104KE02D)
C217  Cap_F: 4.7µF  VDC_V: 35V  [0805_HV]  (hidden comment: C2012X7R1V475K125AC)
C218  VDC_V: 50V  ValueDisplayed: 0.1uF  [0402L]  (hidden comment: GCM155R71H104KE02D)
C219  Cap_F: 330nF  VDC_V: 50V  [0603L]  (hidden comment: C1608X7R1H334K080AC)
C220  VDC_V: 25V  ValueDisplayed: 0.1uF  [0402L]  (hidden comment: GRM155R71E104KE14D)
C221  Cap_F: 2.2µF  VDC_V: 16V  [0603L]  (hidden comment: EMK107BB7225KA-T)
C222  VDC_V: 25V  ValueDisplayed: 0.1uF  [0402L]  (hidden comment: GRM155R71E104KE14D)
C223  TempCo: C0G/NP0  ValueDisplayed: 1000pF  [0402L]  (hidden comment: CGA2B2C0G1H102J050BA)
C224  TempCo: C0G/NP0  ValueDisplayed: 0.022uF  [0402L]  (hidden comment: GCM155R71H223KA55D)
C225  ValueDisplayed: 100pF  [0402L]  (hidden comment: GRM1555C1H101JA01D)
C226  VDC_V: 25V  ValueDisplayed: 0.1uF  [0402L]  (hidden comment: GRM155R71E104KE14D)
C227  VDC_V: 25V  ValueDisplayed: 300pF  [0402L]  (hidden comment: GRM1555C1E301JA01D)
C228  ValueDisplayed: 100pF  [0402L]  (hidden comment: GRM1555C1H101JA01D)
C230  TempCo: C0G/NP0  ValueDisplayed: 1000pF  [0402L]  (hidden comment: CGA2B2C0G1H102J050BA)
C413  VDC_V: 50V  ValueDisplayed: 10uF  [1206_180L]  (hidden comment: CL31B106KBHNNNE)
C414  VDC_V: 50V  ValueDisplayed: 10uF  [1206_180L]  (hidden comment: CL31B106KBHNNNE)
C415  VDC_V: 50V  ValueDisplayed: 0.1uF  [0402S]  (hidden comment: GCM155R71H104KE02D)
C416  VDC_V: 50V  ValueDisplayed: 0.1uF  [0402L]  (hidden comment: GCM155R71H104KE02D)
C418  VDC_V: 25V  ValueDisplayed: 0.1uF  [0402S]  (hidden comment: GRM155R71E104KE14D)
C419  VDC_V: 50V  ValueDisplayed: 330pF  [0402S]  (hidden comment: CGA2B2X7R1H331K050BA)
C420  VDC_V: 50V  ValueDisplayed: 330pF  [0402S]  (hidden comment: CGA2B2X7R1H331K050BA)
C421  VDC_V: 50V  ValueDisplayed: 10uF  [1206_180L]  (hidden comment: CL31B106KBHNNNE)
C422  VDC_V: 50V  ValueDisplayed: 10uF  [1206_180L]  (hidden comment: CL31B106KBHNNNE)
C423  VDC_V: 50V  ValueDisplayed: 0.1uF  [0402S]  (hidden comment: GCM155R71H104KE02D)
C424  VDC_V: 50V  ValueDisplayed: 0.1uF  [0402L]  (hidden comment: GCM155R71H104KE02D)
C426  VDC_V: 25V  ValueDisplayed: 0.1uF  [0402S]  (hidden comment: GRM155R71E104KE14D)
C427  VDC_V: 50V  ValueDisplayed: 330pF  [0402S]  (hidden comment: CGA2B2X7R1H331K050BA)
C428  VDC_V: 50V  ValueDisplayed: 330pF  [0402S]  (hidden comment: CGA2B2X7R1H331K050BA)
C431  VDC_V: 50V  ValueDisplayed: 0.1uF  [0402S]  (hidden comment: GCM155R71H104KE02D)
C432  VDC_V: 50V  ValueDisplayed: 0.1uF  [0402S]  (hidden comment: GCM155R71H104KE02D)
C433  VDC_V: 50V  ValueDisplayed: 0.1uF  [0402S]  (hidden comment: GCM155R71H104KE02D)
C450  VDC_V: 25V  ValueDisplayed: 0.1uF  [0402L]  (hidden comment: GRM155R71E104KE14D)
C451  Cap_F: 2.2µF  VDC_V: 16V  [0603L]  (hidden comment: EMK107BB7225KA-T)
C476  ValueDisplayed: 100pF  [0402L]  (hidden comment: GRM1555C1H101JA01D)
C477  ValueDisplayed: 100pF  [0402L]  (hidden comment: GRM1555C1H101JA01D)
C478  ValueDisplayed: 100pF  [0402L]  (hidden comment: GRM1555C1H101JA01D)
D10  US1Q-TP  [FP-US1Q-TP_SMA-MFG]
D11  US1Q-TP  [FP-US1Q-TP_SMA-MFG]
D12  US1Q-TP  [FP-US1Q-TP_SMA-MFG]
D19  NSR0130P2T5G  [SOD-923]
D20  NSR0130P2T5G  [SOD-923]
D21  NSR0130P2T5G  [SOD-923]
D22  value Green  [WL-SMCW_GREEN]  (hidden comment: 150060VS75000)
D23  value Green  [WL-SMCW_GREEN]  (hidden comment: 150060VS75000)
D24  value Green  [WL-SMCW_GREEN]  (hidden comment: 150060VS75000)
FB10  74269244182  [FP-74269244182_0402-MFG]  (value not drawn)
FB11  74269244182  [FP-74269244182_0402-MFG]  (value not drawn)
FB12  74269244182  [FP-74269244182_0402-MFG]  (value not drawn)
L7  74279228260  [0603L]  (value not drawn)
NT9  Net-Tie  [Net-Tie7milsWide_20milsLong]  (net tie, no BOM)
NT19  Net-Tie  [Net-Tie7milsWide_20milsLong]  (net tie, no BOM)
NT25  Net-Tie  [Net-Tie7milsWide_20milsLong]  (net tie, no BOM)
NT26  Net-Tie  [Net-Tie7milsWide_20milsLong]  (net tie, no BOM)
R82  ValueDisplayed: 10.0k  [0402L]  (hidden comment: CRCW040210K0FKED)
R83  ValueDisplayed: 10.0k  [0402L]  (hidden comment: CRCW040210K0FKED)
R84  ValueDisplayed: 10.0k  [0402L]  (hidden comment: CRCW040210K0FKED)
R186  ValueDisplayed: 249  [0402L]  (hidden comment: ERJ-2RKF2490X)
R187  ValueDisplayed: 100k  [0402S]  (hidden comment: ERJ-2GEJ104X)
R188  ValueDisplayed: 30.0k  [0402L]  (hidden comment: CRCW040230K0FKED)
R189  ValueDisplayed: 390  [0805_HV]  (hidden comment: ERJ-6GEYJ391V)
R190  ValueDisplayed: 66.5k  [0402L]  (hidden comment: CRCW040266K5FKED)
R191  ValueDisplayed: 30.0k  [0402L]  (hidden comment: CRCW040230K0FKED)
R193  ValueDisplayed: 10.0k  [0402S]  (hidden comment: MCS0402MD1002BE100)
R194  ValueDisplayed: 10.0k  [0402S]  (hidden comment: MCS0402MD1002BE100)
R195  ValueDisplayed: 49.9k  [0402S]  (hidden comment: PCF0402-03-49K9BT1)
R196  ValueDisplayed: 0  [0603L]  (hidden comment: RCS06030000Z0EA)
R197  ValueDisplayed: 10.0k  [0402L]  (hidden comment: CRCW040210K0FKED)
R198  ValueDisplayed: 10.0k  [0402L]  (hidden comment: CRCW040210K0FKED)
R199  ValueDisplayed: 10.0k  [0402L]  (hidden comment: CRCW040210K0FKED)
R200  ValueDisplayed: 10.0k  [0402L]  (hidden comment: CRCW040210K0FKED)
R201  ValueDisplayed: 0  [0603L]  (hidden comment: RC0603JR-070RL)
R202  ValueDisplayed: 14.7k  [0603L]  (hidden comment: ERJ-3EKF1472V)
R203  ValueDisplayed: 0  [1206]  (hidden comment: CRCW12060000Z0EA)
R204  ValueDisplayed: 0  [1206]  (hidden comment: CRCW12060000Z0EA)
R205  ValueDisplayed: 11.0k  [0603L]  (hidden comment: RC0603FR-0711KL)
R206  ValueDisplayed: 100  [0402L]  (hidden comment: ERJ-2RKF1000X)
R208  ValueDisplayed: 2.00k  [0402L]  (hidden comment: CRCW04022K00FKED)
R210  ValueDisplayed: 0  [0603L]  (hidden comment: RCS06030000Z0EA)
R211  ValueDisplayed: 0  [0603L]  (hidden comment: RCS06030000Z0EA)
R212  ValueDisplayed: 10.0k  [0402L]  (hidden comment: CRCW040210K0FKED)
R213  ValueDisplayed: 10.0k  [0402L]  (hidden comment: CRCW040210K0FKED)
R214  ValueDisplayed: 10.0k  [0402L]  (hidden comment: CRCW040210K0FKED)
R215  ValueDisplayed: 10.0k  [0402L]  (hidden comment: CRCW040210K0FKED)
R216  ValueDisplayed: 0  [0603L]  (hidden comment: RC0603JR-070RL)
R217  ValueDisplayed: 14.7k  [0603L]  (hidden comment: ERJ-3EKF1472V)
R218  ValueDisplayed: 0  [1206]  (hidden comment: CRCW12060000Z0EA)
R219  ValueDisplayed: 0  [1206]  (hidden comment: CRCW12060000Z0EA)
R220  ValueDisplayed: 11.0k  [0603L]  (hidden comment: RC0603FR-0711KL)
R221  ValueDisplayed: 100  [0402L]  (hidden comment: ERJ-2RKF1000X)
R223  ValueDisplayed: 2.00k  [0402L]  (hidden comment: CRCW04022K00FKED)
R227  ValueDisplayed: 10.0k  [0402L]  (hidden comment: CRCW040210K0FKED)
R228  ValueDisplayed: 10.0k  [0402L]  (hidden comment: CRCW040210K0FKED)
R229  ValueDisplayed: 10.0k  [0402L]  (hidden comment: CRCW040210K0FKED)
R230  ValueDisplayed: 10.0k  [0402L]  (hidden comment: CRCW040210K0FKED)
R231  ValueDisplayed: 0  [0603L]  (hidden comment: RC0603JR-070RL)
R232  ValueDisplayed: 14.7k  [0603L]  (hidden comment: ERJ-3EKF1472V)
R233  ValueDisplayed: 0  [1206]  (hidden comment: CRCW12060000Z0EA)
R234  ValueDisplayed: 7.50k  [0402L]  (hidden comment: ERA-2AEB752X)
R235  ValueDisplayed: 0  [1206]  (hidden comment: CRCW12060000Z0EA)
R236  ValueDisplayed: 11.0k  [0603L]  (hidden comment: RC0603FR-0711KL)
R237  ValueDisplayed: 100  [0402L]  (hidden comment: ERJ-2RKF1000X)
R238  Value1: 0.1%  ValueDisplayed: 10.0  [CPF0402]  (hidden comment: CPF0402B10RE1)
R239  ValueDisplayed: 10.0k  [0402L]  (hidden comment: MCS0402MD1002BE100)
R240  ValueDisplayed: 309  [0402L]  (hidden comment: CRCW0402309RFKED)
R241  ValueDisplayed: 10.0k  [0402L]  (hidden comment: MCS0402MD1002BE100)
R243  Value1: 0.1%  ValueDisplayed: 10.0  [CPF0402]  (hidden comment: CPF0402B10RE1)
R244  ValueDisplayed: 7.50k  [0402L]  (hidden comment: ERA-2AEB752X)
R245  ValueDisplayed: 2.00k  [0402L]  (hidden comment: CRCW04022K00FKED)
R252  ValueDisplayed: 66.5k  [0402L]  (hidden comment: CRCW040266K5FKED)
R253  ValueDisplayed: 30.0k  [0402L]  (hidden comment: CRCW040230K0FKED)
R281  ValueDisplayed: 66.5k  [0402L]  (hidden comment: CRCW040266K5FKED)
R302  ValueDisplayed: 30.0k  [0402L]  (hidden comment: CRCW040230K0FKED)
R351  ValueDisplayed: 0  [0402L]  (hidden comment: RC0402JR-070RL)
R353  ValueDisplayed: 0  [0402L]  (hidden comment: RC0402JR-070RL)
R446  ValueDisplayed: 0  [0402L]  (hidden comment: RC0402JR-070RL)
R527  ValueDisplayed: 2.00k  [0402L]  (hidden comment: CRCW04022K00FKED)
R528  ValueDisplayed: 100k  [0402S]  (hidden comment: ERJ-2GEJ104X)
R529  ValueDisplayed: 30.0k  [0402L]  (hidden comment: CRCW040230K0FKED)
R532  ValueDisplayed: 10.0k  [0402S]  (hidden comment: MCS0402MD1002BE100)
R533  ValueDisplayed: 10.0k  [0402S]  (hidden comment: MCS0402MD1002BE100)
R534  ValueDisplayed: 49.9k  [0402S]  (hidden comment: PCF0402-03-49K9BT1)
R535  ValueDisplayed: 249  [0402L]  (hidden comment: ERJ-2RKF2490X)
R536  ValueDisplayed: 100k  [0402S]  (hidden comment: ERJ-2GEJ104X)
R537  ValueDisplayed: 30.0k  [0402L]  (hidden comment: CRCW040230K0FKED)
R540  ValueDisplayed: 10.0k  [0402S]  (hidden comment: MCS0402MD1002BE100)
R541  ValueDisplayed: 10.0k  [0402S]  (hidden comment: MCS0402MD1002BE100)
R542  ValueDisplayed: 49.9k  [0402S]  (hidden comment: PCF0402-03-49K9BT1)
R555  ValueDisplayed: 2.00k  [0402L]  (hidden comment: CRCW04022K00FKED)
R556  ValueDisplayed: 2.00k  [0402L]  (hidden comment: CRCW04022K00FKED)
R557  ValueDisplayed: 249  [0402L]  (hidden comment: ERJ-2RKF2490X)
R560  ValueDisplayed: 2.0k  [1206]  (hidden comment: CRCW12062K00JNEA)
R561  ValueDisplayed: 2.0k  [1206]  (hidden comment: CRCW12062K00JNEA)
R562  ValueDisplayed: 2.0k  [1206]  (hidden comment: CRCW12062K00JNEA)
TP11  5001  [Keystone5001]  (value not drawn)
TP12  5011  [Keystone5011]  (value not drawn)
TP14  5001  [Keystone5001]  (value not drawn)
TP17  5001  [Keystone5001]  (value not drawn)
TP41  S2751-46R  [Harwin_S2751-46R]  (value not drawn)
TP42  S2751-46R  [Harwin_S2751-46R]  (value not drawn)
TP43  S2751-46R  [Harwin_S2751-46R]  (value not drawn)
TP44  S2751-46R  [Harwin_S2751-46R]  (value not drawn)
TP45  S2751-46R  [Harwin_S2751-46R]  (value not drawn)
TP46  S2751-46R  [Harwin_S2751-46R]  (value not drawn)
TP47  S2751-46R  [Harwin_S2751-46R]  (value not drawn)
TP48  S2751-46R  [Harwin_S2751-46R]  (value not drawn)
TP49  S2751-46R  [Harwin_S2751-46R]  (value not drawn)
U8  OPA2392DR  [D0008A-MFG]  (part A of 2)
U23  UCC14341BQDWNRQ1  [DWN0036A-MFG]
U25  UCC21710QDWQ1  [DW0016B_HV]
U26  UCC21710QDWQ1  [DW0016B_HV]
U27  UCC21710QDWQ1  [DW0016B_HV]
U28  AMC1302DWVR  [DWV0008A]
U57  UCC14341BQDWNRQ1  [DWN0036A-MFG]
U58  UCC14341BQDWNRQ1  [DWN0036A-MFG]

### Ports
DESAT_BOT_L1 (bidir), DESAT_BOT_L2 (bidir), DESAT_BOT_L3 (bidir), EN_DCDC_GATES_BUF (bidir), GATE_BOT_L1 (bidir), GATE_BOT_L2 (bidir), GATE_BOT_L3 (bidir), GATES_FLT_L1 (bidir), GATES_FLT_L2 (bidir), GATES_FLT_L3 (bidir), GATES_RDY (bidir), GATES_RST (bidir), I_NEG_RAIL+ (bidir), I_NEG_RAIL- (bidir), I_SENSE_VDC_NEG (bidir), PWM2_BUF_L1 (bidir), PWM2_BUF_L2 (bidir), PWM2_BUF_L3 (bidir)

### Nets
1.65V: C223.2 R234.2
+3V3: R187.2 R198.2 R199.2 R200.2 R201.2 R213.2 R214.2 R215.2 R216.2 R228.2 R229.2 R230.2 R231.2 R528.2 R536.2
+3V3_Ua: L7.2
+3V3_Ua2: C450.1 C451.1 U8.8(V+)
+5VISO_DC-: C222.1 U28.1(VDD1)
+12V: C431.1 C432.1 C433.1 FB10.1 FB11.1 FB12.1
+15V_VDC-1: C178.2 C179.1 C188.2 C190.1 C191.2 C192.1 D22.2(A) R190.2 R202.2 TP41.1 U23.28(VDD) U23.29(VDD) U25.5(VDD)
+15V_VDC-2: C182.1 C203.1 C204.2 C205.1 C206.2 C416.2 D23.2(A) R217.2 R252.2 TP42.1 U26.5(VDD) U57.28(VDD) U57.29(VDD)
+15V_VDC-3: C193.1 C216.1 C217.2 C218.1 C219.2 C424.2 D24.2(A) R232.2 R281.2 TP47.1 U27.5(VDD) U58.28(VDD) U58.29(VDD)
-4V_VDC-1: C178.1 C179.2 C181.2 C187.2 C188.1 C189.1 C190.2 NT19.1 R189.1 R560.1 TP45.1 U23.19(VEE) U23.20(VEE) U23.21(VEE) U23.22(VEE) U23.23(VEE) U23.24(VEE) U23.25(VEE) U23.26(VEE) U23.27(VEE) U23.30(VEE) U23.31(VEE) U23.36(VEE) U25.8(VEE)
-4V_VDC-2: C182.2 C200.2 C202.1 C203.2 C204.1 C416.1 NT25.1 R561.1 TP46.1 U26.8(VEE) U57.19(VEE) U57.20(VEE) U57.21(VEE) U57.22(VEE) U57.23(VEE) U57.24(VEE) U57.25(VEE) U57.26(VEE) U57.27(VEE) U57.30(VEE) U57.31(VEE) U57.36(VEE)
-4V_VDC-3: C193.2 C213.2 C215.1 C216.2 C217.1 C424.1 NT26.1 R562.1 TP49.1 U27.8(VEE) U58.19(VEE) U58.20(VEE) U58.21(VEE) U58.22(VEE) U58.23(VEE) U58.24(VEE) U58.25(VEE) U58.26(VEE) U58.27(VEE) U58.30(VEE) U58.31(VEE) U58.36(VEE)
GND: C172.2 C173.2 C174.2 C183.2 C186.2 C194.2 C195.2 C199.2 C207.2 C208.2 C212.2 C220.2 C221.2 C225.2 C226.2 C227.2 C413.2 C414.2 C415.2 C418.2 C421.2 C422.2 C423.2 C426.2 C431.2 C432.2 C433.2 C450.2 C451.2 C476.1 C477.1 C478.1 R193.1 R197.1 R212.1 R227.1 R532.1 R540.1 TP11.1 TP12.1 TP14.1 TP17.1 U8.4(V-) U23.1(GNDP) U23.2(GNDP) U23.5(GNDP) U23.8(GNDP) U23.9(GNDP) U23.10(GNDP) U23.11(GNDP) U23.12(GNDP) U23.13(GNDP) U23.14(GNDP) U23.15(GNDP) U23.16(GNDP) U23.17(GNDP) U23.18(GNDP) U25.9(GND) U25.11(IN-) U26.9(GND) U26.11(IN-) U27.9(GND) U27.11(IN-) U28.5(GND2) U57.1(GNDP) U57.2(GNDP) U57.5(GNDP) U57.8(GNDP) U57.9(GNDP) U57.10(GNDP) U57.11(GNDP) U57.12(GNDP) U57.13(GNDP) U57.14(GNDP) U57.15(GNDP) U57.16(GNDP) U57.17(GNDP) U57.18(GNDP) U58.1(GNDP) U58.2(GNDP) U58.5(GNDP) U58.8(GNDP) U58.9(GNDP) U58.10(GNDP) U58.11(GNDP) U58.12(GNDP) U58.13(GNDP) U58.14(GNDP) U58.15(GNDP) U58.16(GNDP) U58.17(GNDP) U58.18(GNDP)  [also labelled GNDP]
REF_VDC-1: C181.1 C187.1 C189.2 C191.1 C192.2 C196.2 R82.1 R186.2 R189.2 R191.2 R208.1 R555.1 TP43.1 U25.1(AIN) U25.3(COM)
REF_VDC-2: C200.1 C202.2 C205.2 C206.1 C209.2 R83.1 R223.1 R253.2 R527.1 R535.2 TP44.1 U26.1(AIN) U26.3(COM)
REF_VDC-3: C213.1 C215.2 C218.2 C219.1 C228.2 R84.1 R245.1 R302.2 R556.1 R557.2 TP48.1 U27.1(AIN) U27.3(COM)
VDC-_REF: C222.2 NT9.1 U28.4(GND1)
VEEA_VDC-1: C184.2 C185.2 NT19.2 R194.1 R195.1 U23.35(VEEA)
VEEA_VDC-2: C419.2 C420.2 NT25.2 R533.1 R534.1 U57.35(VEEA)
VEEA_VDC-3: C427.2 C428.2 NT26.2 R541.1 R542.1 U58.35(VEEA)
~{PG_VDC-}: R187.1 U23.3(~{PG})
~{PG_VDC-2}: R528.1 U57.3(~{PG})
~{PG_VDC-3}: R536.1 U58.3(~{PG})
AMC13x_VDD_LO: C220.1 C221.1 L7.1 U28.8(VDD2)
AMC1302_OUTN_B: R241.2 U28.6(VOUTN)
AMC1302_OUTP_B: R239.2 U28.7(VOUTP)
DESAT_BOT_L1: D10.1(CATHODE) ; port DESAT_BOT_L1
DESAT_BOT_L2: D11.1(CATHODE) ; port DESAT_BOT_L2
DESAT_BOT_L3: D12.1(CATHODE) ; port DESAT_BOT_L3
EN_DCDC_GATES_BUF: R351.1 R353.1 R446.1 ; port EN_DCDC_GATES_BUF
FBVDD_VDC-1: C184.1 R190.1 R194.2 U23.34(FBVDD)
FBVDD_VDC-2: C419.1 R252.1 R533.2 U57.34(FBVDD)
FBVDD_VDC-3: C427.1 R281.1 R541.2 U58.34(FBVDD)
FBVEE_VDC-1: C185.1 R191.1 R195.2 U23.33(FBVEE)
FBVEE_VDC-2: C420.1 R253.1 R534.2 U57.33(FBVEE)
FBVEE_VDC-3: C428.1 R302.1 R542.2 U58.33(FBVEE)
GATE_BOT_L1: R82.2 R203.2 R204.2 U25.7(CLMPI) ; port GATE_BOT_L1
GATE_BOT_L2: R83.2 R218.2 R219.2 U26.7(CLMPI) ; port GATE_BOT_L2
GATE_BOT_L3: R84.2 R233.2 R235.2 U27.7(CLMPI) ; port GATE_BOT_L3
GATES_FLT_L1: R199.1 U25.13(~{FLT}) ; port GATES_FLT_L1
GATES_FLT_L2: R214.1 U26.13(~{FLT}) ; port GATES_FLT_L2
GATES_FLT_L3: R229.1 U27.13(~{FLT}) ; port GATES_FLT_L3
GATES_RDY: C476.2 C477.2 C478.2 R198.1 R213.1 R228.1 U25.12(RDY) U26.12(RDY) U27.12(RDY) ; port GATES_RDY
GATES_RST: R206.1 R221.1 R237.1 ; port GATES_RST
I_NEG_RAIL+: R238.1 ; port I_NEG_RAIL+
I_NEG_RAIL-: NT9.2 R243.1 ; port I_NEG_RAIL-
I_SENSE_VDC_NEG: C227.1 R240.2 ; port I_SENSE_VDC_NEG
IN+_BOT_L1: C186.1 R196.1 R197.2 U25.10(IN+)
IN+_BOT_L2: C199.1 R210.1 R212.2 U26.10(IN+)
IN+_BOT_L3: C212.1 R211.1 R227.2 U27.10(IN+)
LO_MAG_VIN_L1: C172.1 C173.1 C174.1 FB10.2 R188.2 U23.6(VIN) U23.7(VIN)
LO_MAG_VIN_L2: C413.1 C414.1 C415.1 FB11.2 R529.2 U57.6(VIN) U57.7(VIN)
LO_MAG_VIN_L3: C421.1 C422.1 C423.1 FB12.2 R537.2 U58.6(VIN) U58.7(VIN)
OH_BOT_L1: R204.1 U25.4(OUTH)
OH_BOT_L2: R219.1 U26.4(OUTH)
OH_BOT_L3: R235.1 U27.4(OUTH)
OL_BOT_L1: R203.1 U25.6(OUTL)
OL_BOT_L2: R218.1 U26.6(OUTL)
OL_BOT_L3: R233.1 U27.6(OUTL)
OP_IDCN: C230.2 R240.1 R244.1 U8.1(OUT_A)
PWM2_BUF_L1: R196.2 ; port PWM2_BUF_L1
PWM2_BUF_L2: R210.2 ; port PWM2_BUF_L2
PWM2_BUF_L3: R211.2 ; port PWM2_BUF_L3
RLIM_VDC-1: D19.1(K) R555.2 U23.32(RLIM)
RLIM_VDC-2: D20.1(K) R527.2 U57.32(RLIM)
RLIM_VDC-3: D21.1(K) R556.2 U58.32(RLIM)
RST_BOT_L1: C194.1 R200.1 R206.2 U25.14(~{RST}/EN)
RST_BOT_L2: C207.1 R215.1 R221.2 U26.14(~{RST}/EN)
RST_BOT_L3: C225.1 R230.1 R237.2 U27.14(~{RST}/EN)
VCC_BOT_L1: C195.1 R201.1 U25.15(VCC)
VCC_BOT_L2: C208.1 R216.1 U26.15(VCC)
VCC_BOT_L3: C226.1 R231.1 U27.15(VCC)
VINN_DC-: C224.2 R243.2 U28.3(VINN)
VINP_DC-: C224.1 R238.2 U28.2(VINP)
NetC183_1: C183.1 R188.1 R193.2 R446.2 U23.4(ENA)
NetC196_1: C196.1 R205.1 R208.2 U25.2(OC)
NetC209_1: C209.1 R220.1 R223.2 U26.2(OC)
NetC223_1: C223.1 R234.1 R239.1 U8.3(+IN_A)
NetC228_1: C228.1 R236.1 R245.2 U27.2(OC)
NetC230_1: C230.1 R241.1 R244.2 U8.2(-IN_A)
NetC418_1: C418.1 R351.2 R529.1 R532.2 U57.4(ENA)
NetC426_1: C426.1 R353.2 R537.1 R540.2 U58.4(ENA)
NetD10_2: D10.2(ANODE) R202.1 R205.2
NetD11_2: D11.2(ANODE) R217.1 R220.2
NetD12_2: D12.2(ANODE) R232.1 R236.2
NetD19_2: D19.2(A) R186.1
NetD20_2: D20.2(A) R535.1
NetD21_2: D21.2(A) R557.1
NetD22_1: D22.1(K) R560.2
NetD23_1: D23.1(K) R561.2
NetD24_1: D24.1(K) R562.2

Not connected (* = marked no-connect by the designer): U25 16(APWM); U26 16(APWM); U27 16(APWM)

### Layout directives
net class HV_Nets; net class HV_VDC_LOW: +5VISO_DC-, +15V_VDC-1, +15V_VDC-2, +15V_VDC-3, -4V_VDC-1, -4V_VDC-2, -4V_VDC-3, FBVDD_VDC-1, FBVDD_VDC-2, FBVDD_VDC-3, FBVEE_VDC-1, FBVEE_VDC-2, FBVEE_VDC-3, OH_BOT_L1, OH_BOT_L2, OH_BOT_L3, OL_BOT_L1, OL_BOT_L2, OL_BOT_L3, REF_VDC-1, REF_VDC-2, REF_VDC-3, RLIM_VDC-1, RLIM_VDC-2, RLIM_VDC-3, VDC-_REF, VEEA_VDC-1, VEEA_VDC-2, VEEA_VDC-3, VINN_DC-, VINP_DC-
net class LV Nets: AMC1302_OUTN_B, AMC1302_OUTP_B

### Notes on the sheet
- Gate Drive Bias Supply 15V/-4V
- Placeholder Gate Drive Bias Supply 15V/-4V
- 4x2.3uF
- (near TP43) 4x0.43uF
- 1x0.43uF
- (near R188) 3V
- (near R529) 3V
- 1x2.3uF
- PWR RTN: Pins 8, 9
- (near C181) Vf=2V, ILED=8.5mA
- (near NT19) PWR RTN: Pins 30, 31
- (near R189) Icomp=10mA
- PWR RTN: Pins 30, 31
- (near R196) Src Term. Total R=70
- CVEE = 2.3 uF
- CVDD = 0.43 uF
- CVDD = 1.1 uF
- (near R537) 3V
- (near D10) tbnk = 193ns
- (near D10) VDESAT = 3.95V
- (near D11) VDESAT = 3.95V
- (near R238) f3db = 362kHz
- Charge bucket
- (near D12) VDESAT = 3.95V
- (near C230) f3db = 20kHz

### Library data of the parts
C172 C173 C413 C414 C421 C422 = CMP-0008802-2: as C132 on sheet TIDA-1606-Switching-Node-L3-E7
C174 C178 C187 C190 C192 C200 C203 C205 C213 C216 C218 C415 C416 C423 C424 C431-C433 = CMP-0006356-2: as C134 on sheet TIDA-1606-Switching-Node-L3-E7
C179 C182 C188 C193 C204 C217 = CMP-0007885-2: as C135 on sheet TIDA-1606-Switching-Node-L3-E7
C181 C189 C202 C215 C221 C451 = CMP-0007121-4: as C149 on sheet TIDA-1606-Switching-Node-L3-E7
C183 C195 C208 C220 C222 C226 C418 C426 C450 = CMP-0006659-2: as C143 on sheet TIDA-1606-Switching-Node-L3-E7
C184 C185 C419 C420 C427 C428 = CMP-0006318-2: as C144 on sheet TIDA-1606-Switching-Node-L3-E7
C186 C194 C196 C199 C207 C209 C212 C225 C228 C476-C478 = CMP-0006410-2: as C146 on sheet TIDA-1606-Switching-Node-L3-E7
C191 C206 C219 = CMP-0007048-4: as C151 on sheet TIDA-1606-Switching-Node-L3-E7
C223 C230 = CMP-0006309-2: CAP, CERM, 1000 pF, 50 V, +/- 5%, C0G/NP0, AEC-Q200 Grade 1, 0402; Manufacturer: TDK; TaMin_C: -55°C; Polarized: N; SizeAreaWB_mm2: 3; Value1: Unknown; U/M: EA; Value: 1000pF; TaMax_C: 125°C; SizeZ_mm: 0.6; SizeX_mm: 1; SizeY_mm: 0.5; Cap_Case: 0402; Value2: 50V; AEC Qualified: Y; Cap_F: 1nF; AEC Category: Q200
C224 = CMP-0006358-2: CAP, CERM, 0.022 uF, 50 V, +/- 10%, C0G/NP0, 0402; Manufacturer: MuRata; TaMin_C: -55°C; Polarized: N; SizeAreaWB_mm2: 3; Value1: Unknown; U/M: EA; TaMax_C: 125°C; SizeZ_mm: 0.6; SizeX_mm: 1; SizeY_mm: 0.5; Cap_Case: 0402; Value2: 50V; Cap_F: 22nF; AEC Category: Q200
C227 = CMP-0006376-2: as C340 on sheet TIDA-1606-Switching-Node-L3-E7
D10-D12 = CMP-0095286-1: as D8 on sheet TIDA-1606-Switching-Node-L3-E7
D19-D21 = CMP-0077005-2: as D7 on sheet TIDA-1606-Switching-Node-L3-E7
D22-D24 = CMP-0002894-2: as D31 on sheet TIDA-1606-Switching-Node-L3-E7
FB10-FB12 = CMP-0091663-1: as FB21 on sheet TIDA-1606-Switching-Node-L3-E7
L7 = CMP-0003155-2: Ferrite Bead, 26 ohm @ 100 MHz, 6.5 A, 0603; Manufacturer: Wurth Elektronik; Ztyp@1GHz_Ohm: 35.506; ZTyp@100MHz_Ohm: 26; SizeAreaWB_mm2: 4.68; DCR_ohm: 5m; Value1: 0.005 ohm; Value: 26 ohm; Imax_A: 6.5A; SizeZ_mm: 1; SizeX_mm: 1.6; SizeY_mm: 0.8; SizeArea_mm2: 1.28
NT9 NT19 NT25 NT26 = CMP-0078142-6: Single point connection between nets.
R82-R84 R197-R200 R212-R215 R227-R230 = CMP-0025958-3: as R80 on sheet TIDA-1606-Switching-Node-L3-E7
R186 R535 R557 = CMP-0026688-1: RES, 249, 1%, 0.1 W, AEC-Q200 Grade 0, 0402; Manufacturer: Panasonic; Power_W: 100mW; TempCo: 100 ppm/C; Value_Code: 249R; U/M: EA; Value: 249; EIA_Code: E96; SizeX_mm: 1; SizeY_mm: 0.5; SizeZ_mm: 0.6; Value2: 0.1W; AEC Qualified: Y; VDC_V: 50V; AEC Grade: 0; AEC Category: Q200
R187 R528 R536 = CMP-0026995-2: as R148 on sheet TIDA-1606-Switching-Node-L3-E7
R188 R191 R253 R302 R529 R537 = CMP-0078244-2: as R151 on sheet TIDA-1606-Switching-Node-L3-E7
R189 = CMP-0020715-3: RES, 390, 5%, 0.125 W, AEC-Q200 Grade 0, 0805; Manufacturer: Panasonic; Power_W: 125mW; TempCo: 200 ppm/C; Value_Code: 390R; Value: 390; EIA_Code: E24; SizeX_mm: 2; SizeY_mm: 1.25; SizeZ_mm: 1.45; Value2: 0.125W; SizeArea_mm2: 2.5; AEC Qualified: Y; VDC_V: 150V; AEC Category: Q200; AEC Grade: 0; SizeAreaWB_mm2: 6.75
R190 R252 R281 = CMP-0026502-2: as R150 on sheet TIDA-1606-Switching-Node-L3-E7
R193 R194 R239 R241 R532 R533 R540 R541 = CMP-0077124-1: as R152 on sheet TIDA-1606-Switching-Node-L3-E7
R195 R534 R542 = CMP-0026795-1: as R156 on sheet TIDA-1606-Switching-Node-L3-E7
R196 R210 R211 = CMP-0081973-1: as R157 on sheet TIDA-1606-Switching-Node-L3-E7
R201 R216 R231 = CMP-0025885-5: as R162 on sheet TIDA-1606-Switching-Node-L3-E7
R202 R217 R232 = CMP-0022687-3: as R163 on sheet TIDA-1606-Switching-Node-L3-E7
R203 R204 R218 R219 R233 R235 = CMP-0018573-3: as R164 on sheet TIDA-1606-Switching-Node-L3-E7
R205 R220 R236 = CMP-0022763-5: as R166 on sheet TIDA-1606-Switching-Node-L3-E7
R206 R221 R237 = CMP-0026656-1: as R167 on sheet TIDA-1606-Switching-Node-L3-E7
R208 R223 R245 R527 R555 R556 = CMP-0026227-2: as R147 on sheet TIDA-1606-Switching-Node-L3-E7
R234 R244 = CMP-0026786-1: RES, 7.50 k, 0.1%, 0.063 W, AEC-Q200 Grade 0, 0402; Manufacturer: Panasonic; Power_W: 63mW; TempCo: 25 ppm/C; Value_Code: 7k50; U/M: EA; Value: 7.50k; EIA_Code: E192; Res_ohm: 7.5k; SizeX_mm: 1; SizeY_mm: 0.5; SizeZ_mm: 0.6; Value2: 0.063W; AEC Qualified: Y; VDC_V: 50V; AEC Grade: 0; AEC Category: Q200
R238 R243 = CMP-0026765-1: RES, 10.0, 0.1%, 0.063 W, 0402; Manufacturer: TE Connectivity; Power_W: 63mW; TempCo: 25 ppm/C; Value_Code: 10R0; U/M: EA; Value: 10.0; EIA_Code: E192; Res_ohm: 10; SizeX_mm: 1; SizeY_mm: 0.5; SizeZ_mm: 0.35; Value2: 0.063W; AEC Qualified: N; AEC Category: Q200
R240 = CMP-0026283-2: RES, 309, 1%, 0.063 W, AEC-Q200 Grade 0, 0402; Manufacturer: Vishay-Dale; Power_W: 63mW; TempCo: 100 ppm/C; Value_Code: 309R; Value: 309; EIA_Code: E96; SizeX_mm: 1; SizeY_mm: 0.5; SizeZ_mm: 0.6; Value2: 0.063W; AEC Qualified: Y; VDC_V: 50V; AEC Category: Q200; AEC Grade: 0
R351 R353 R446 = CMP-0027004-2: as R364 on sheet TIDA-1606-Switching-Node-L3-E7
R560-R562 = CMP-0018640-3: as R318 on sheet TIDA-1606-Switching-Node-L3-E7
TP11 TP14 TP17 = CMP-0055138-2: as TP8 on sheet TIDA-1606-Switching-Node-L3-E7
TP12 = CMP-0055148-2: Test Point, Multipurpose, Black, TH; Manufacturer: Keystone Electronics; CNHeader: FALSE; ContactFinish: Silver; Green_REACh: Passed; Green_Lifecycle: Active; CT: TRUE
TP41-TP49 = CMP-0003968-1: Test Point, SMT; Manufacturer: Harwin
U8 = CMP-0121707-1: Precision, Low-Offset-Voltage, Low-Noise, Low-Input-Bias-Current, Rail-to-Rail I/O, e-trim™ Operational Amplifiers; Manufacturer: Texas Instruments; SizeZ_mm: 1.75mm; AEC Qualified: No; Gain Bandwidth: 13MHz; Input Bias Current: 0.00000001uA; Input Offset Voltage: 0.001mV; Max Dual Supply Voltage: 2.75V; Max Supply Voltage: 5.5V; Min Dual Supply Voltage: 850mV; Min Supply Voltage: 1.7V; Nominal Supply Current: 1.22mA; Number Of Channels: 2; Output Current Per Channel: 65mA; Response Time: 1us; Standoff Height: 0.11mm; TaMax_C: +125°C; TaMin_C: -40°C; TJmax_C: +150°C; Voltage Gain: 132dB
U23 U57 U58 = CMP-0121477-1: as U17 on sheet TIDA-1606-Switching-Node-L3-E7
U25-U27 = CMP-0080534-2: as U19 on sheet TIDA-1606-Switching-Node-L3-E7
U28 = CMP-0080672-1: Precision Reinforced Isolated Amplifier for Current Sensing, DWV0008A (SOIC-8); Alternate Manufacturer: Texas Instruments; SizeAreaWB_mm2: 105.975; SizeZ_mm: 2.8; SizeX_mm: 11.5; SizeY_mm: 5.85; SizeArea_mm2: 67.275; CompType: IC; AEC Qualified: N; AEC Category: Q200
